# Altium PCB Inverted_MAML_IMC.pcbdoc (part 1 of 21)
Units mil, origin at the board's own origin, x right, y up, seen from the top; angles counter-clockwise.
Board outline 7677.1 x 6771.6 mil, 6 copper layers (Top Layer, Inner1, Inner2, Inner3, Inner4, Bottom Layer), stack 60.7 mil thick; 2732 components, 1531 nets, 7765 pads, 3705 vias.
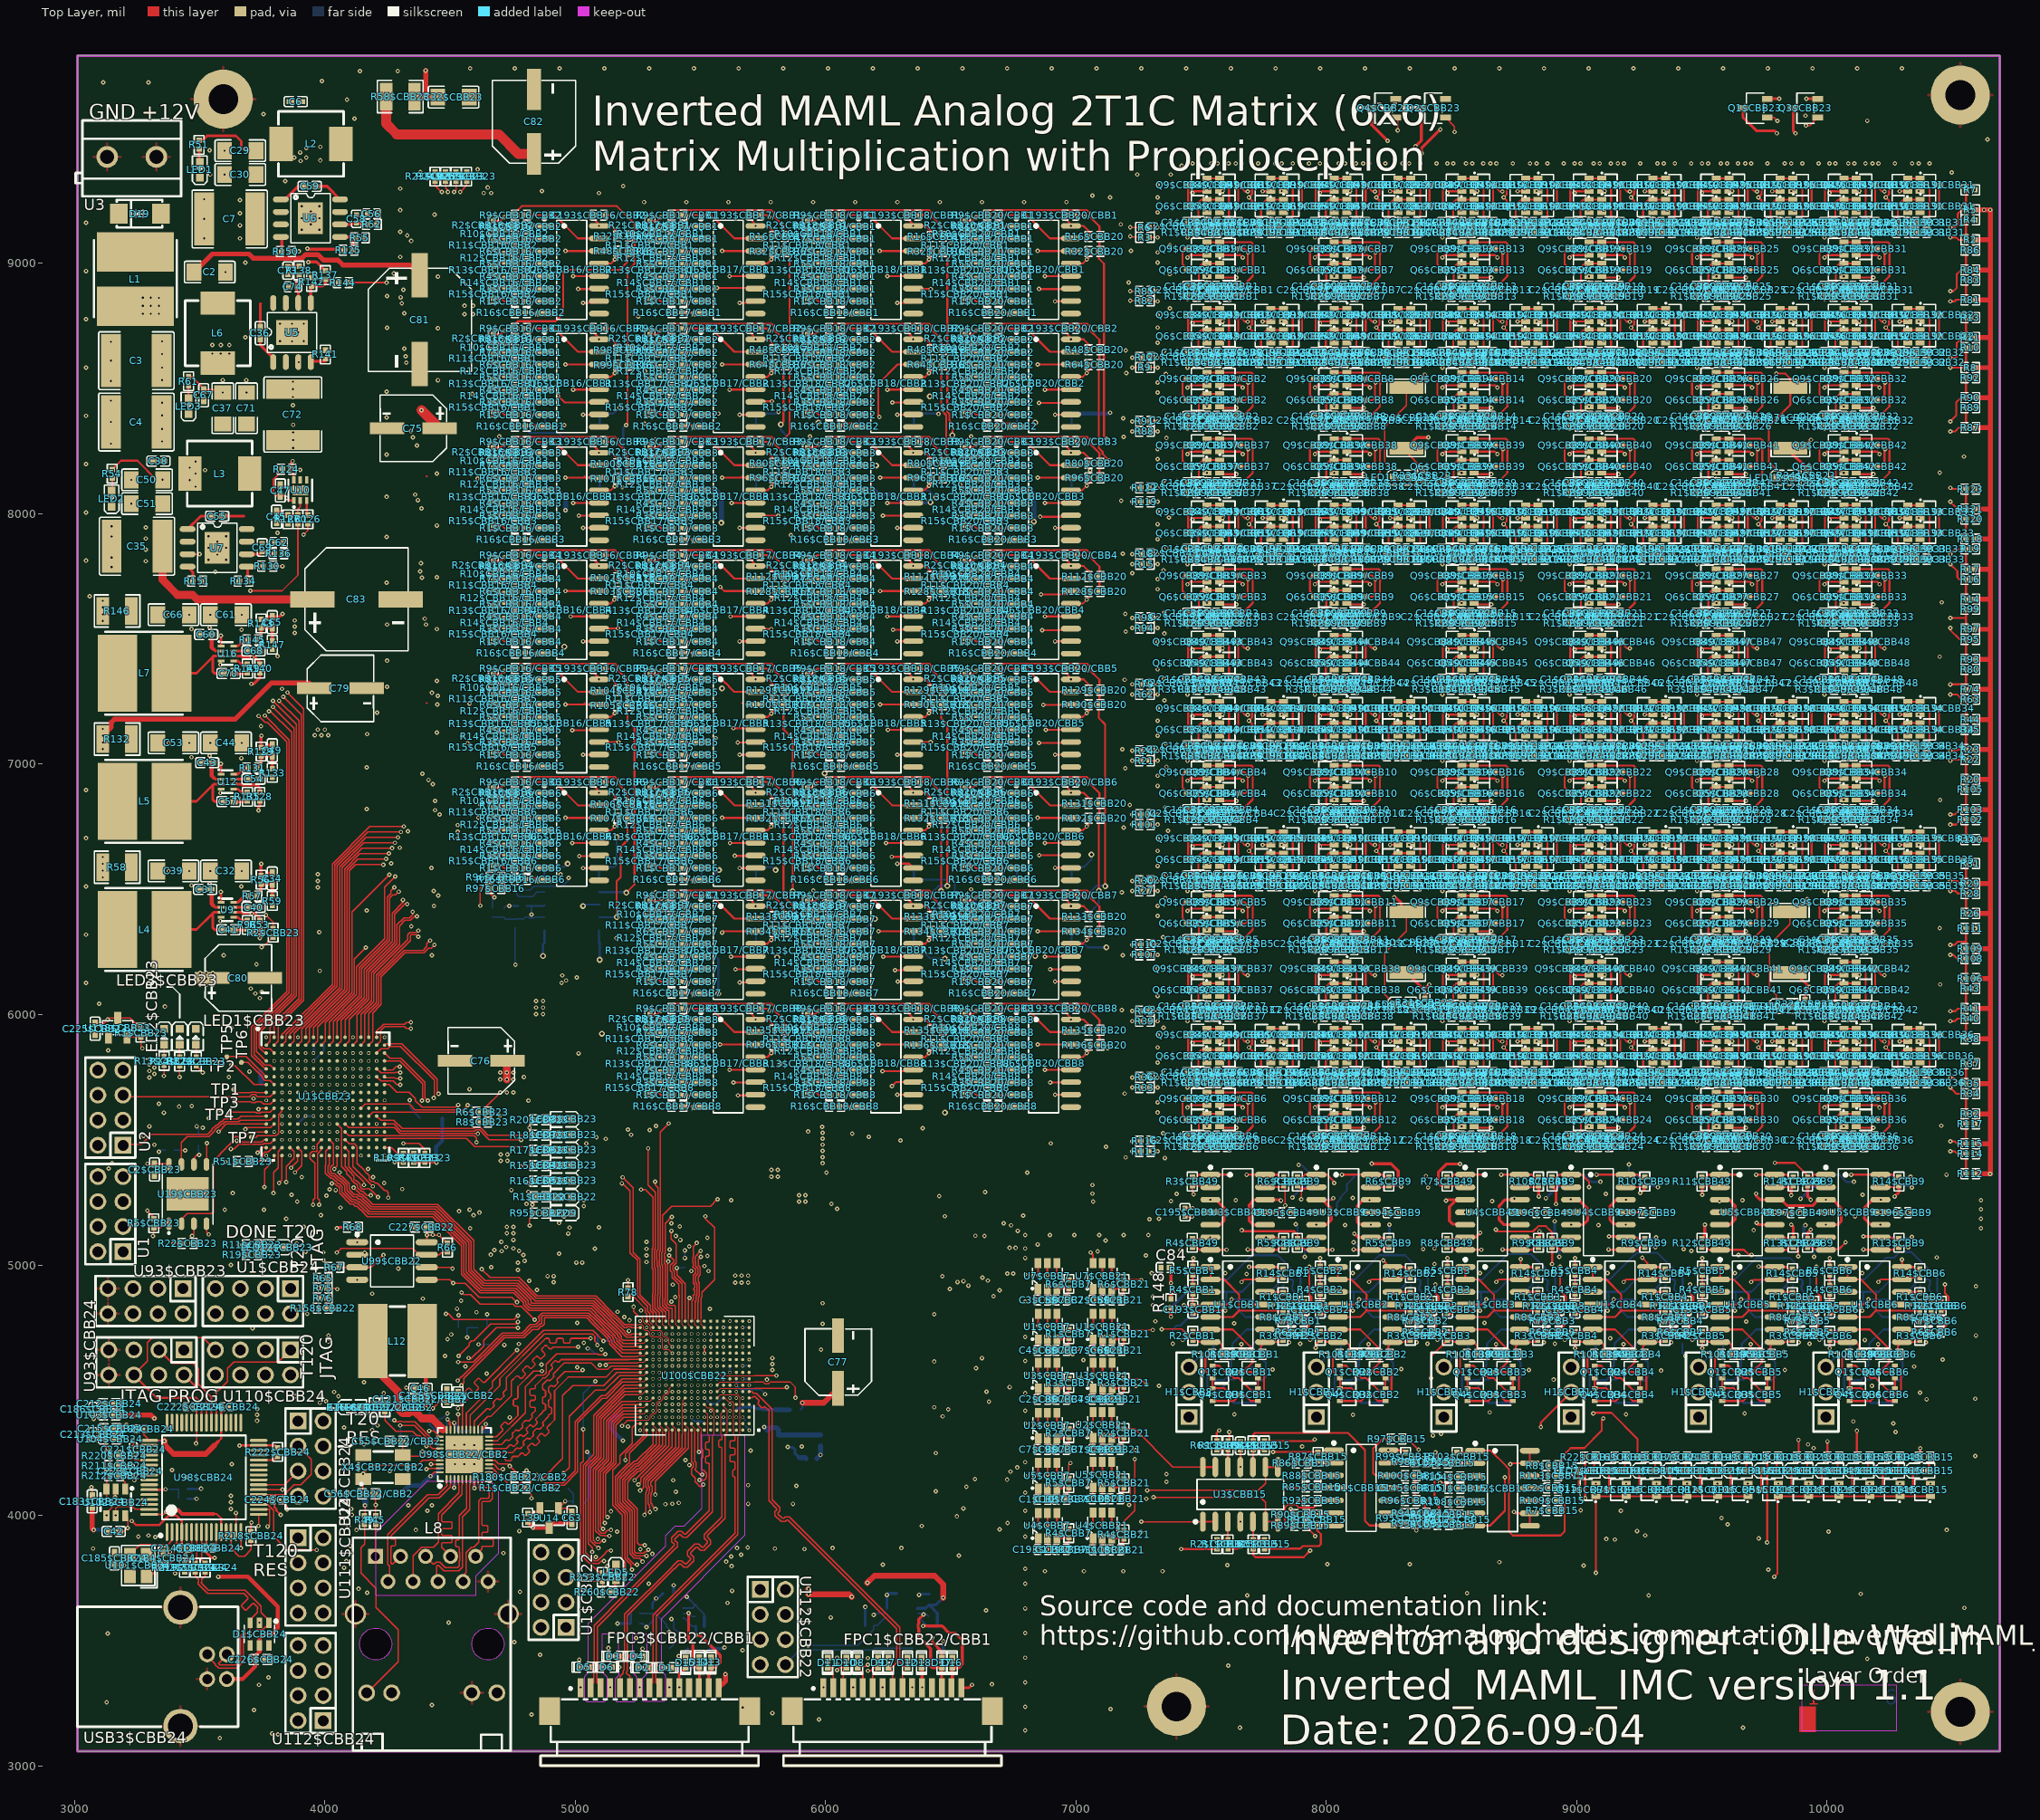
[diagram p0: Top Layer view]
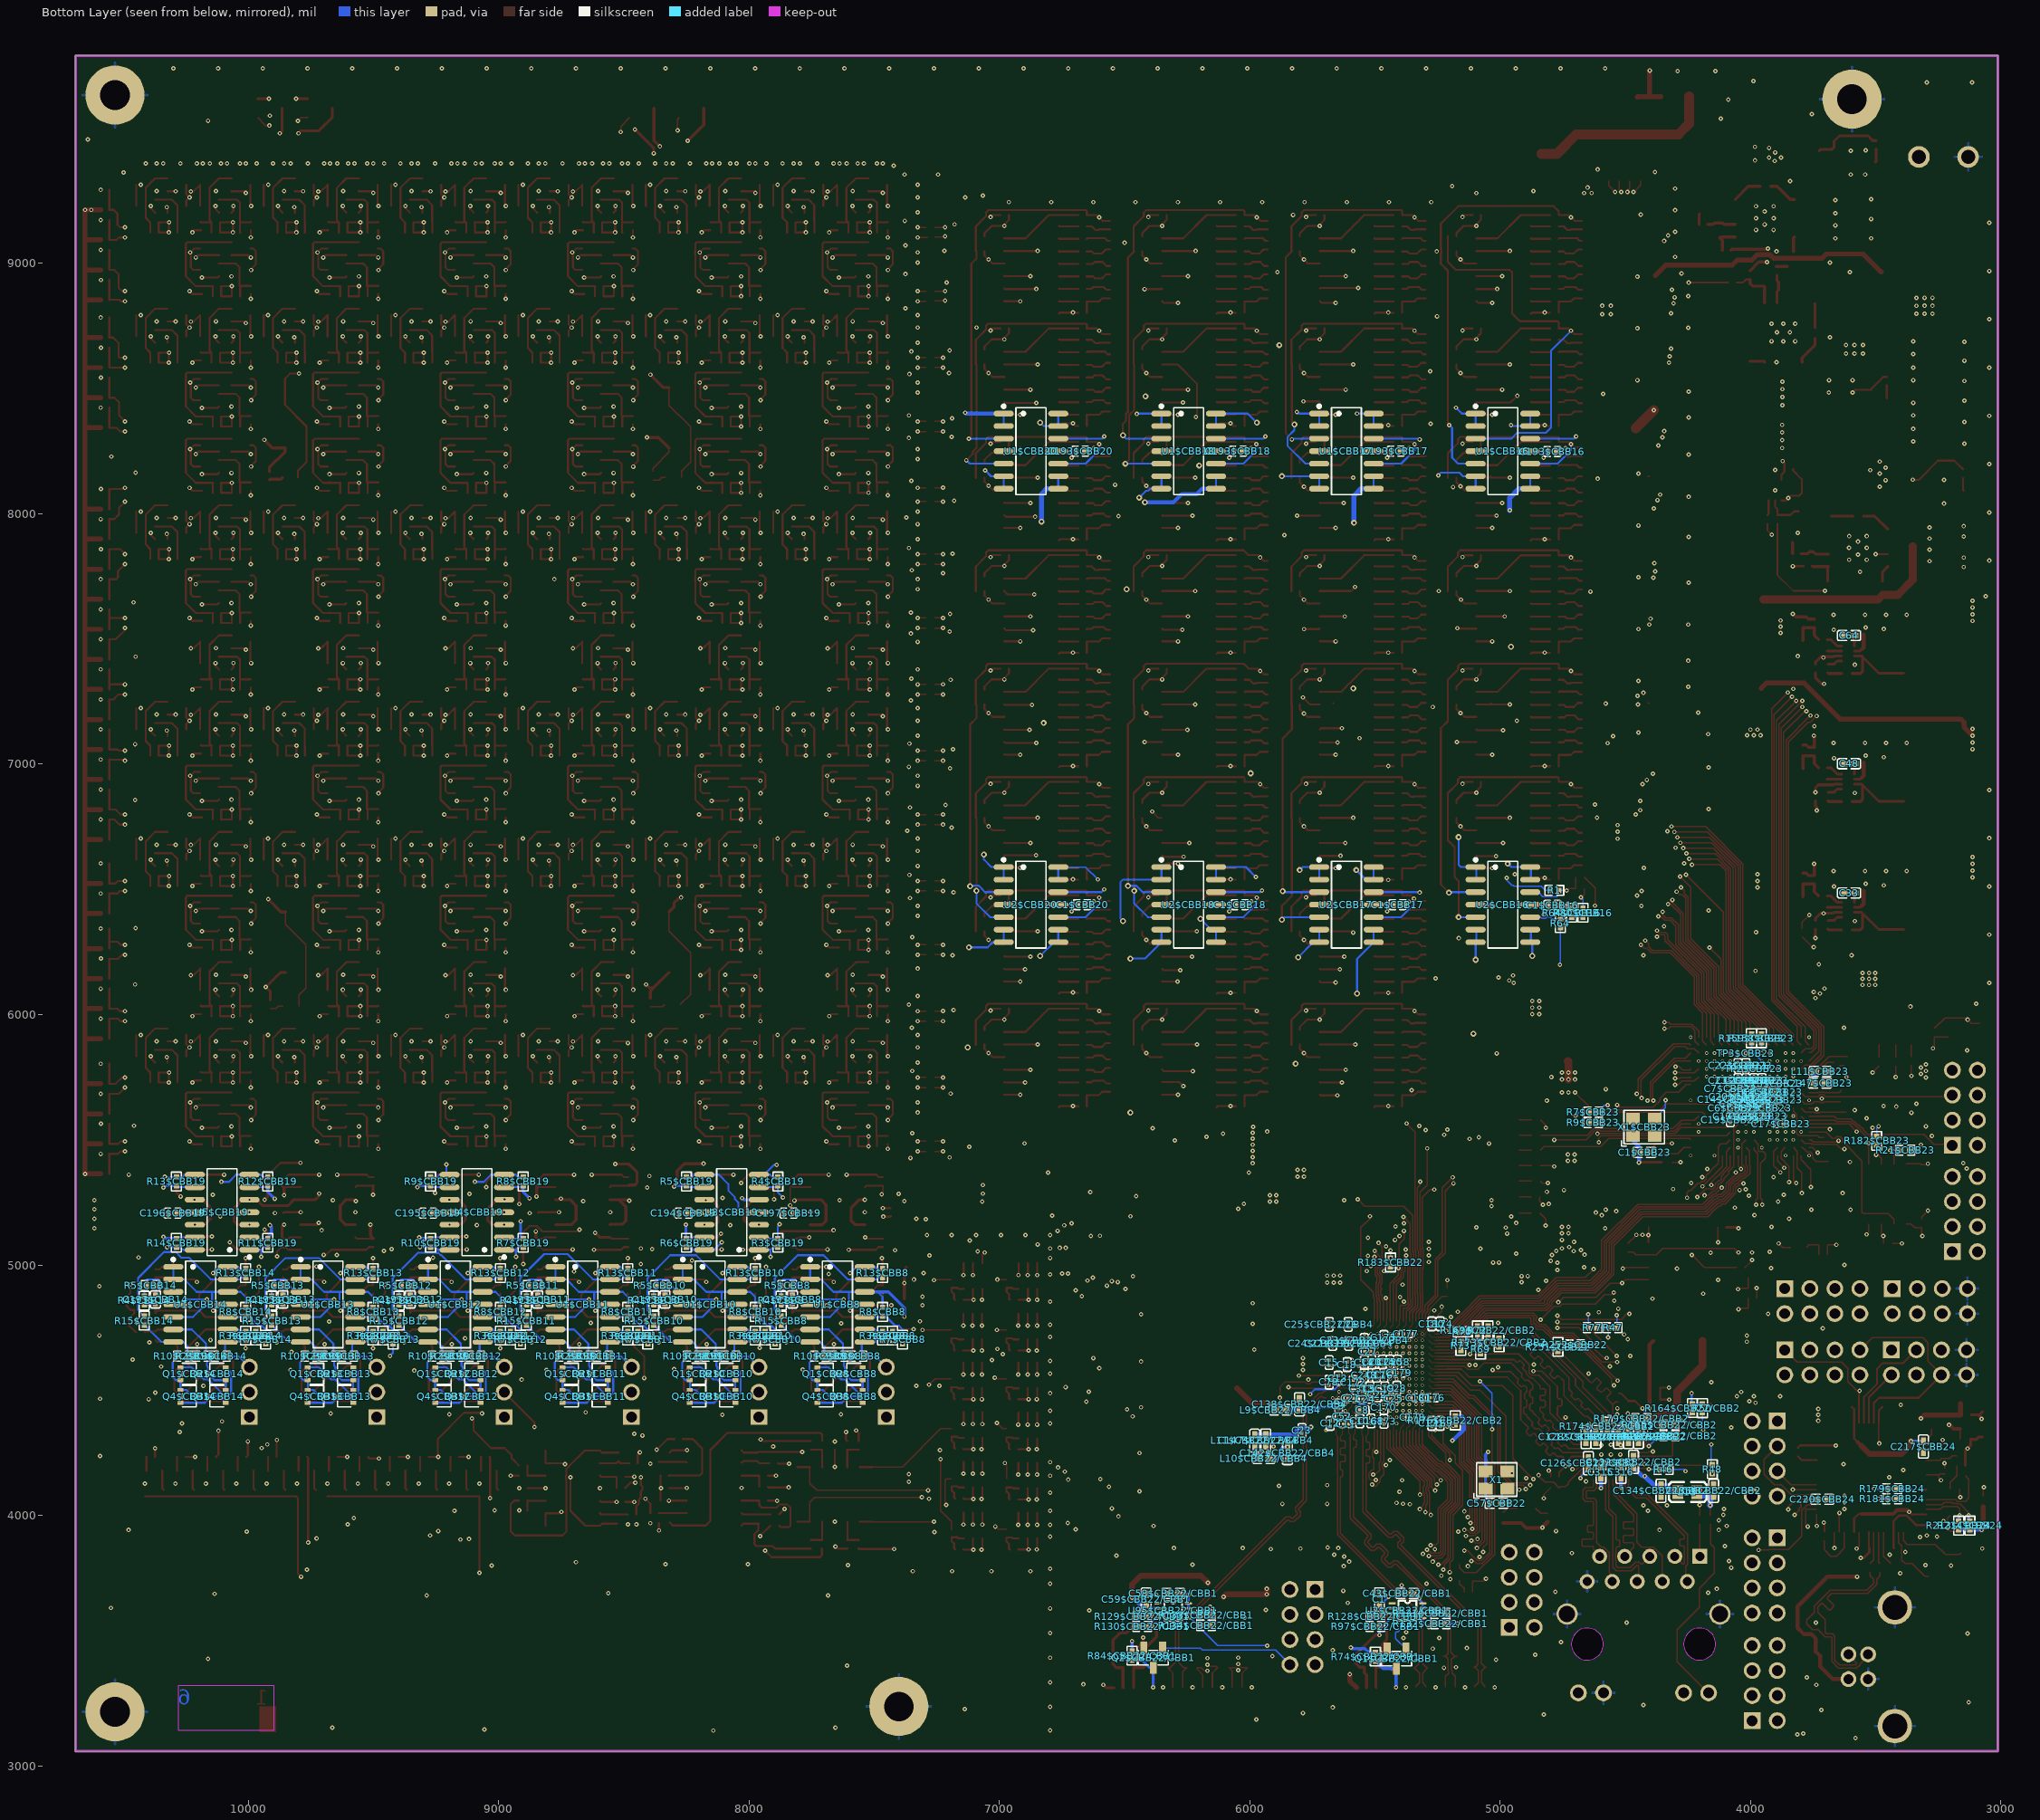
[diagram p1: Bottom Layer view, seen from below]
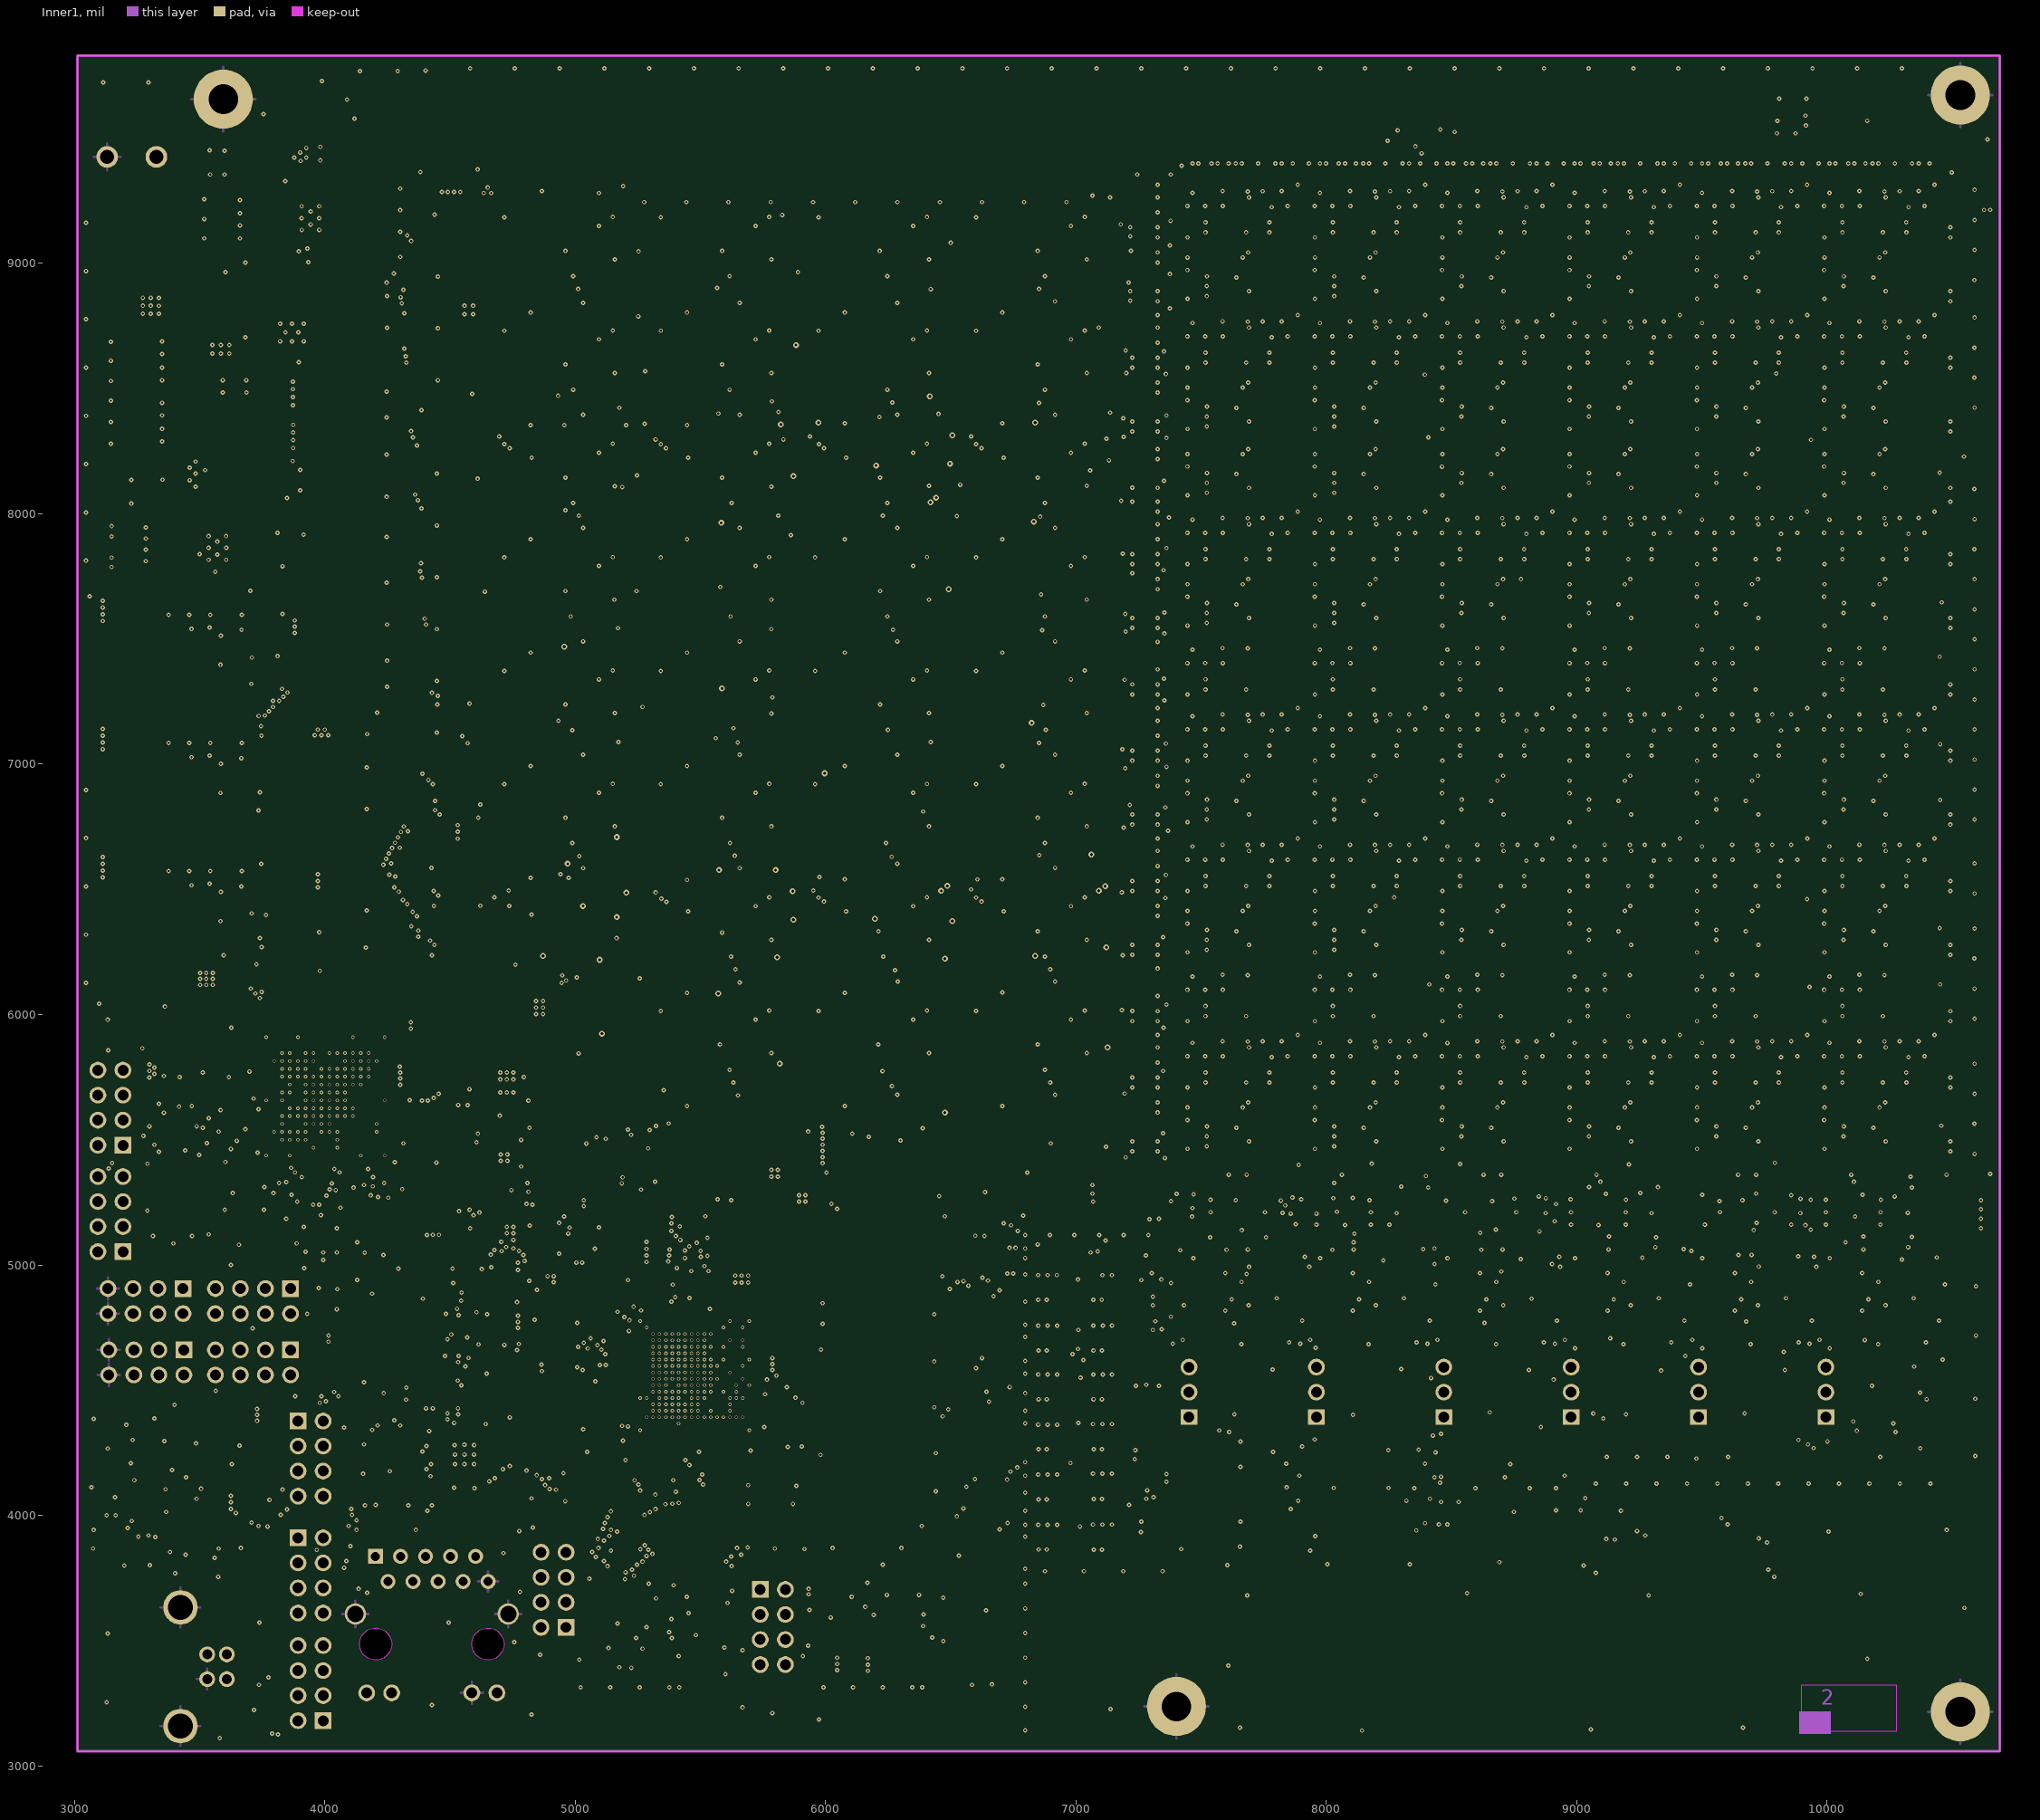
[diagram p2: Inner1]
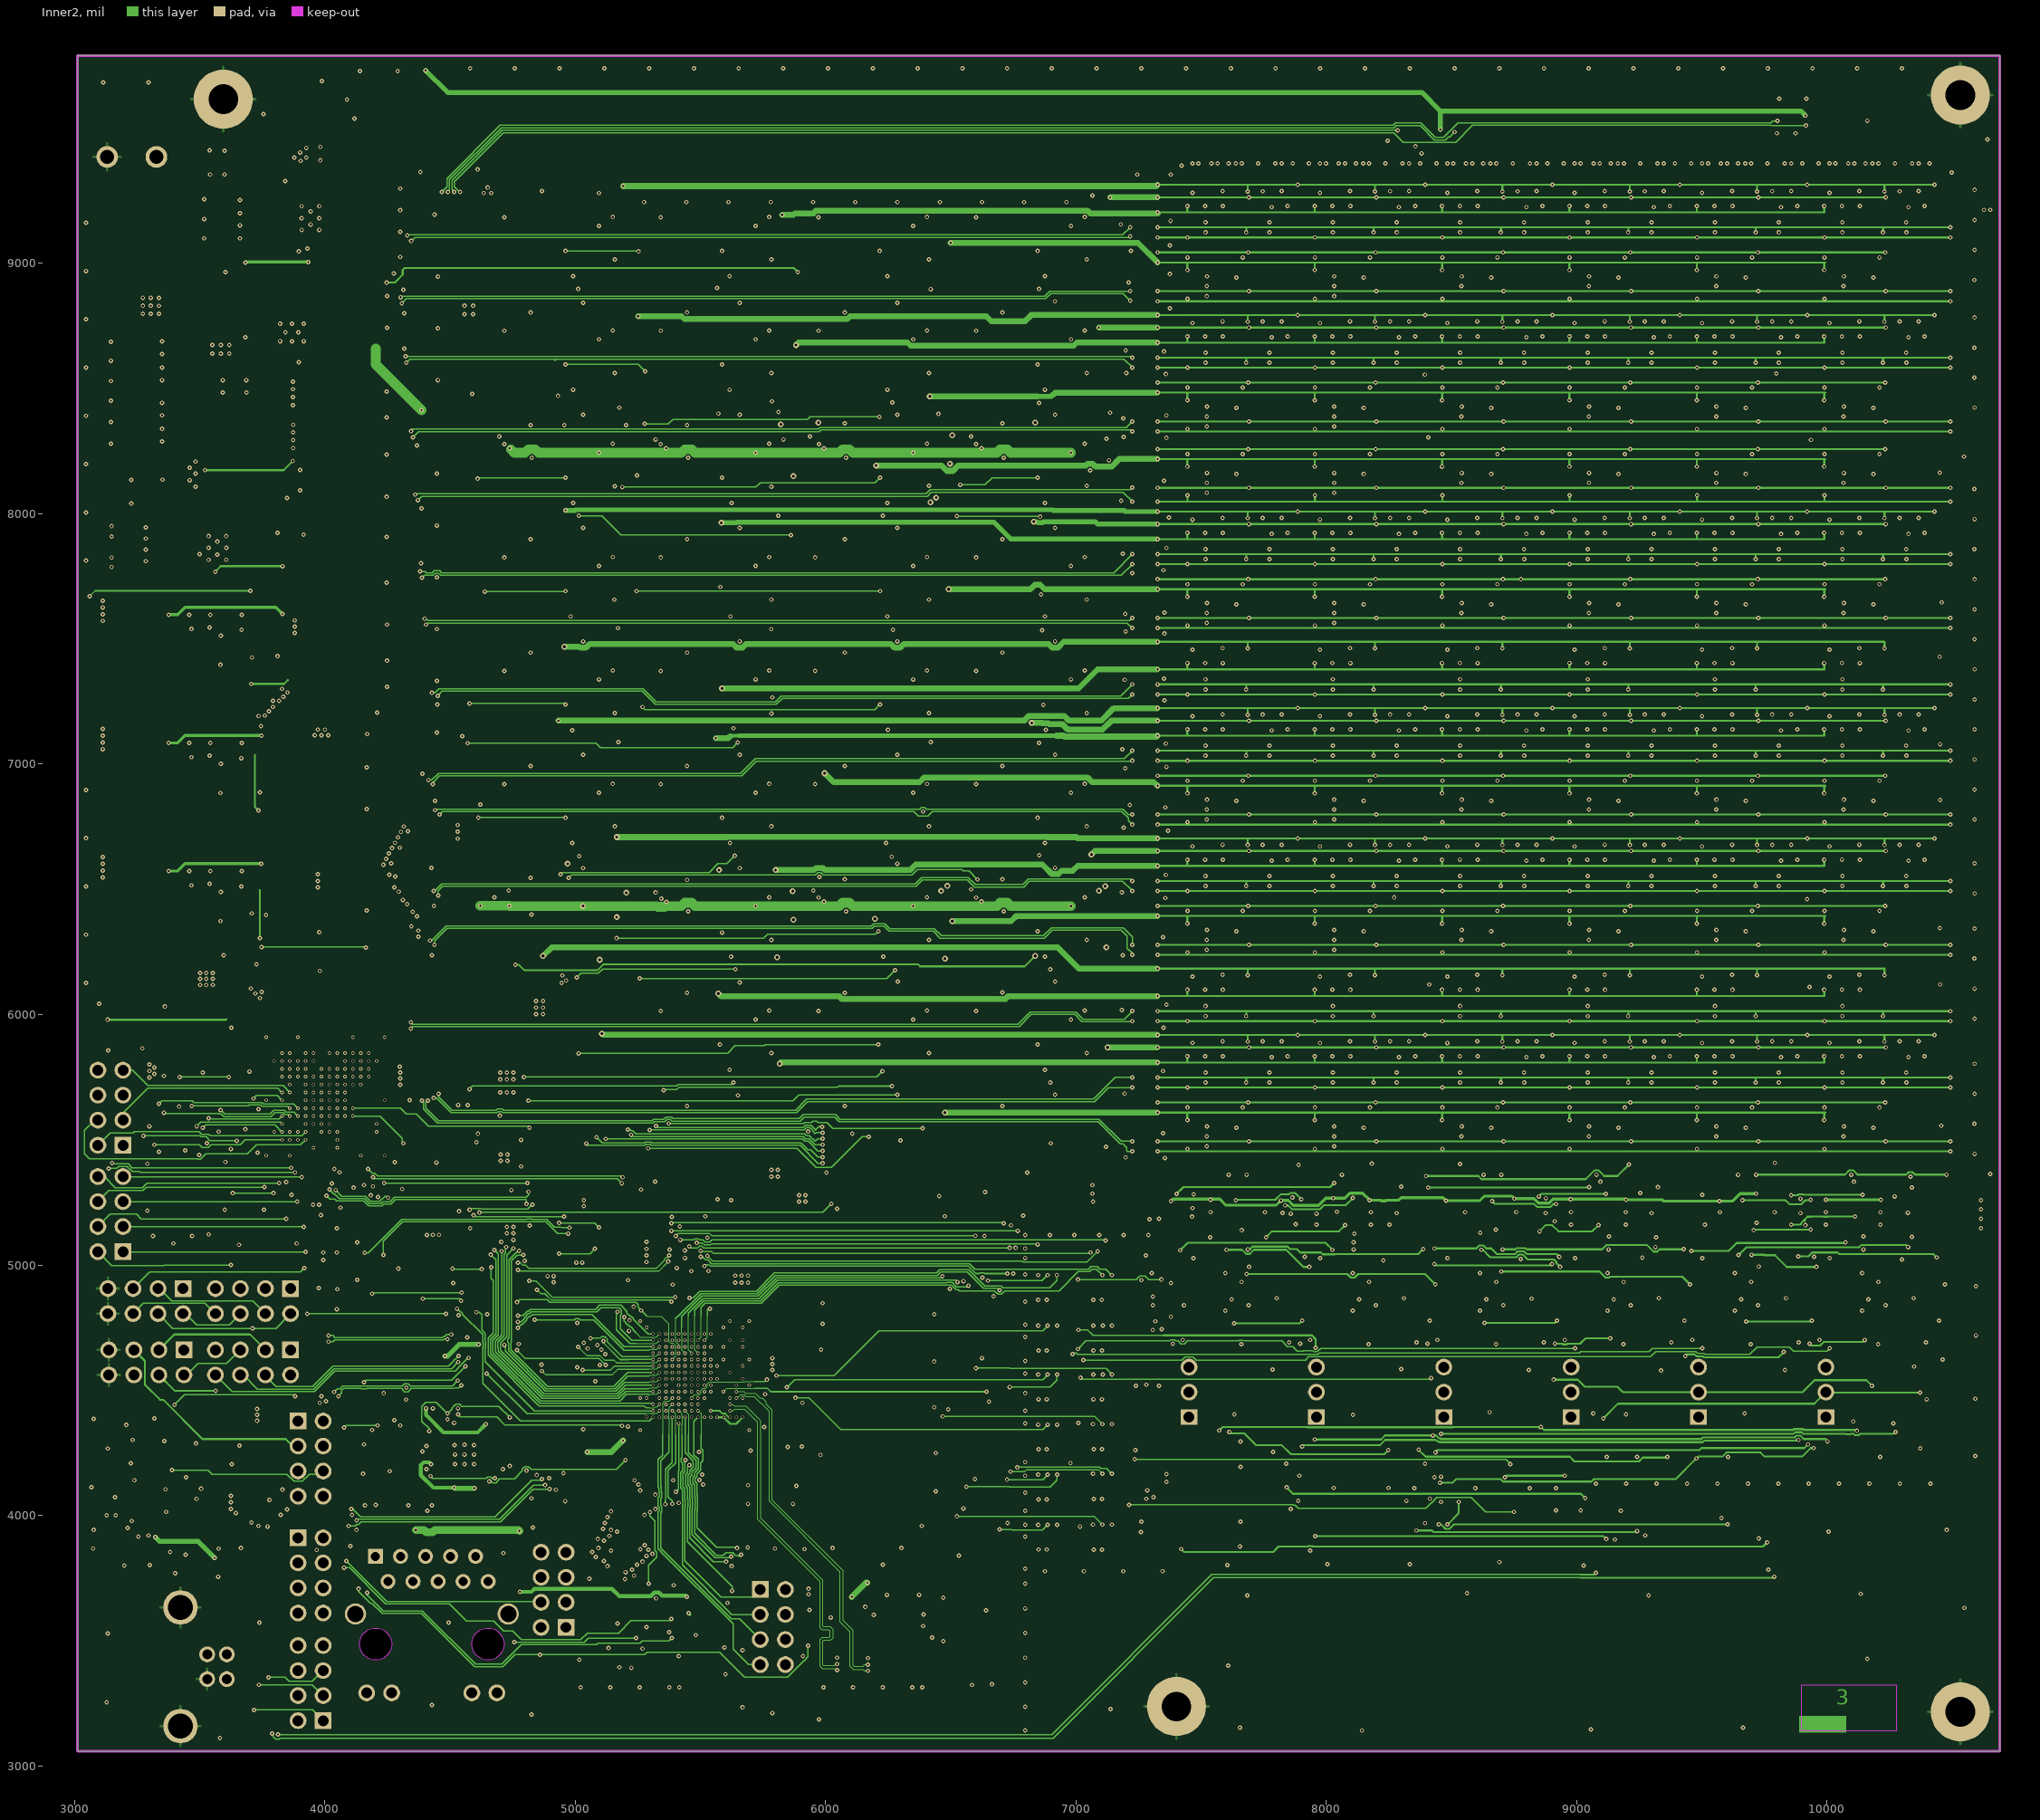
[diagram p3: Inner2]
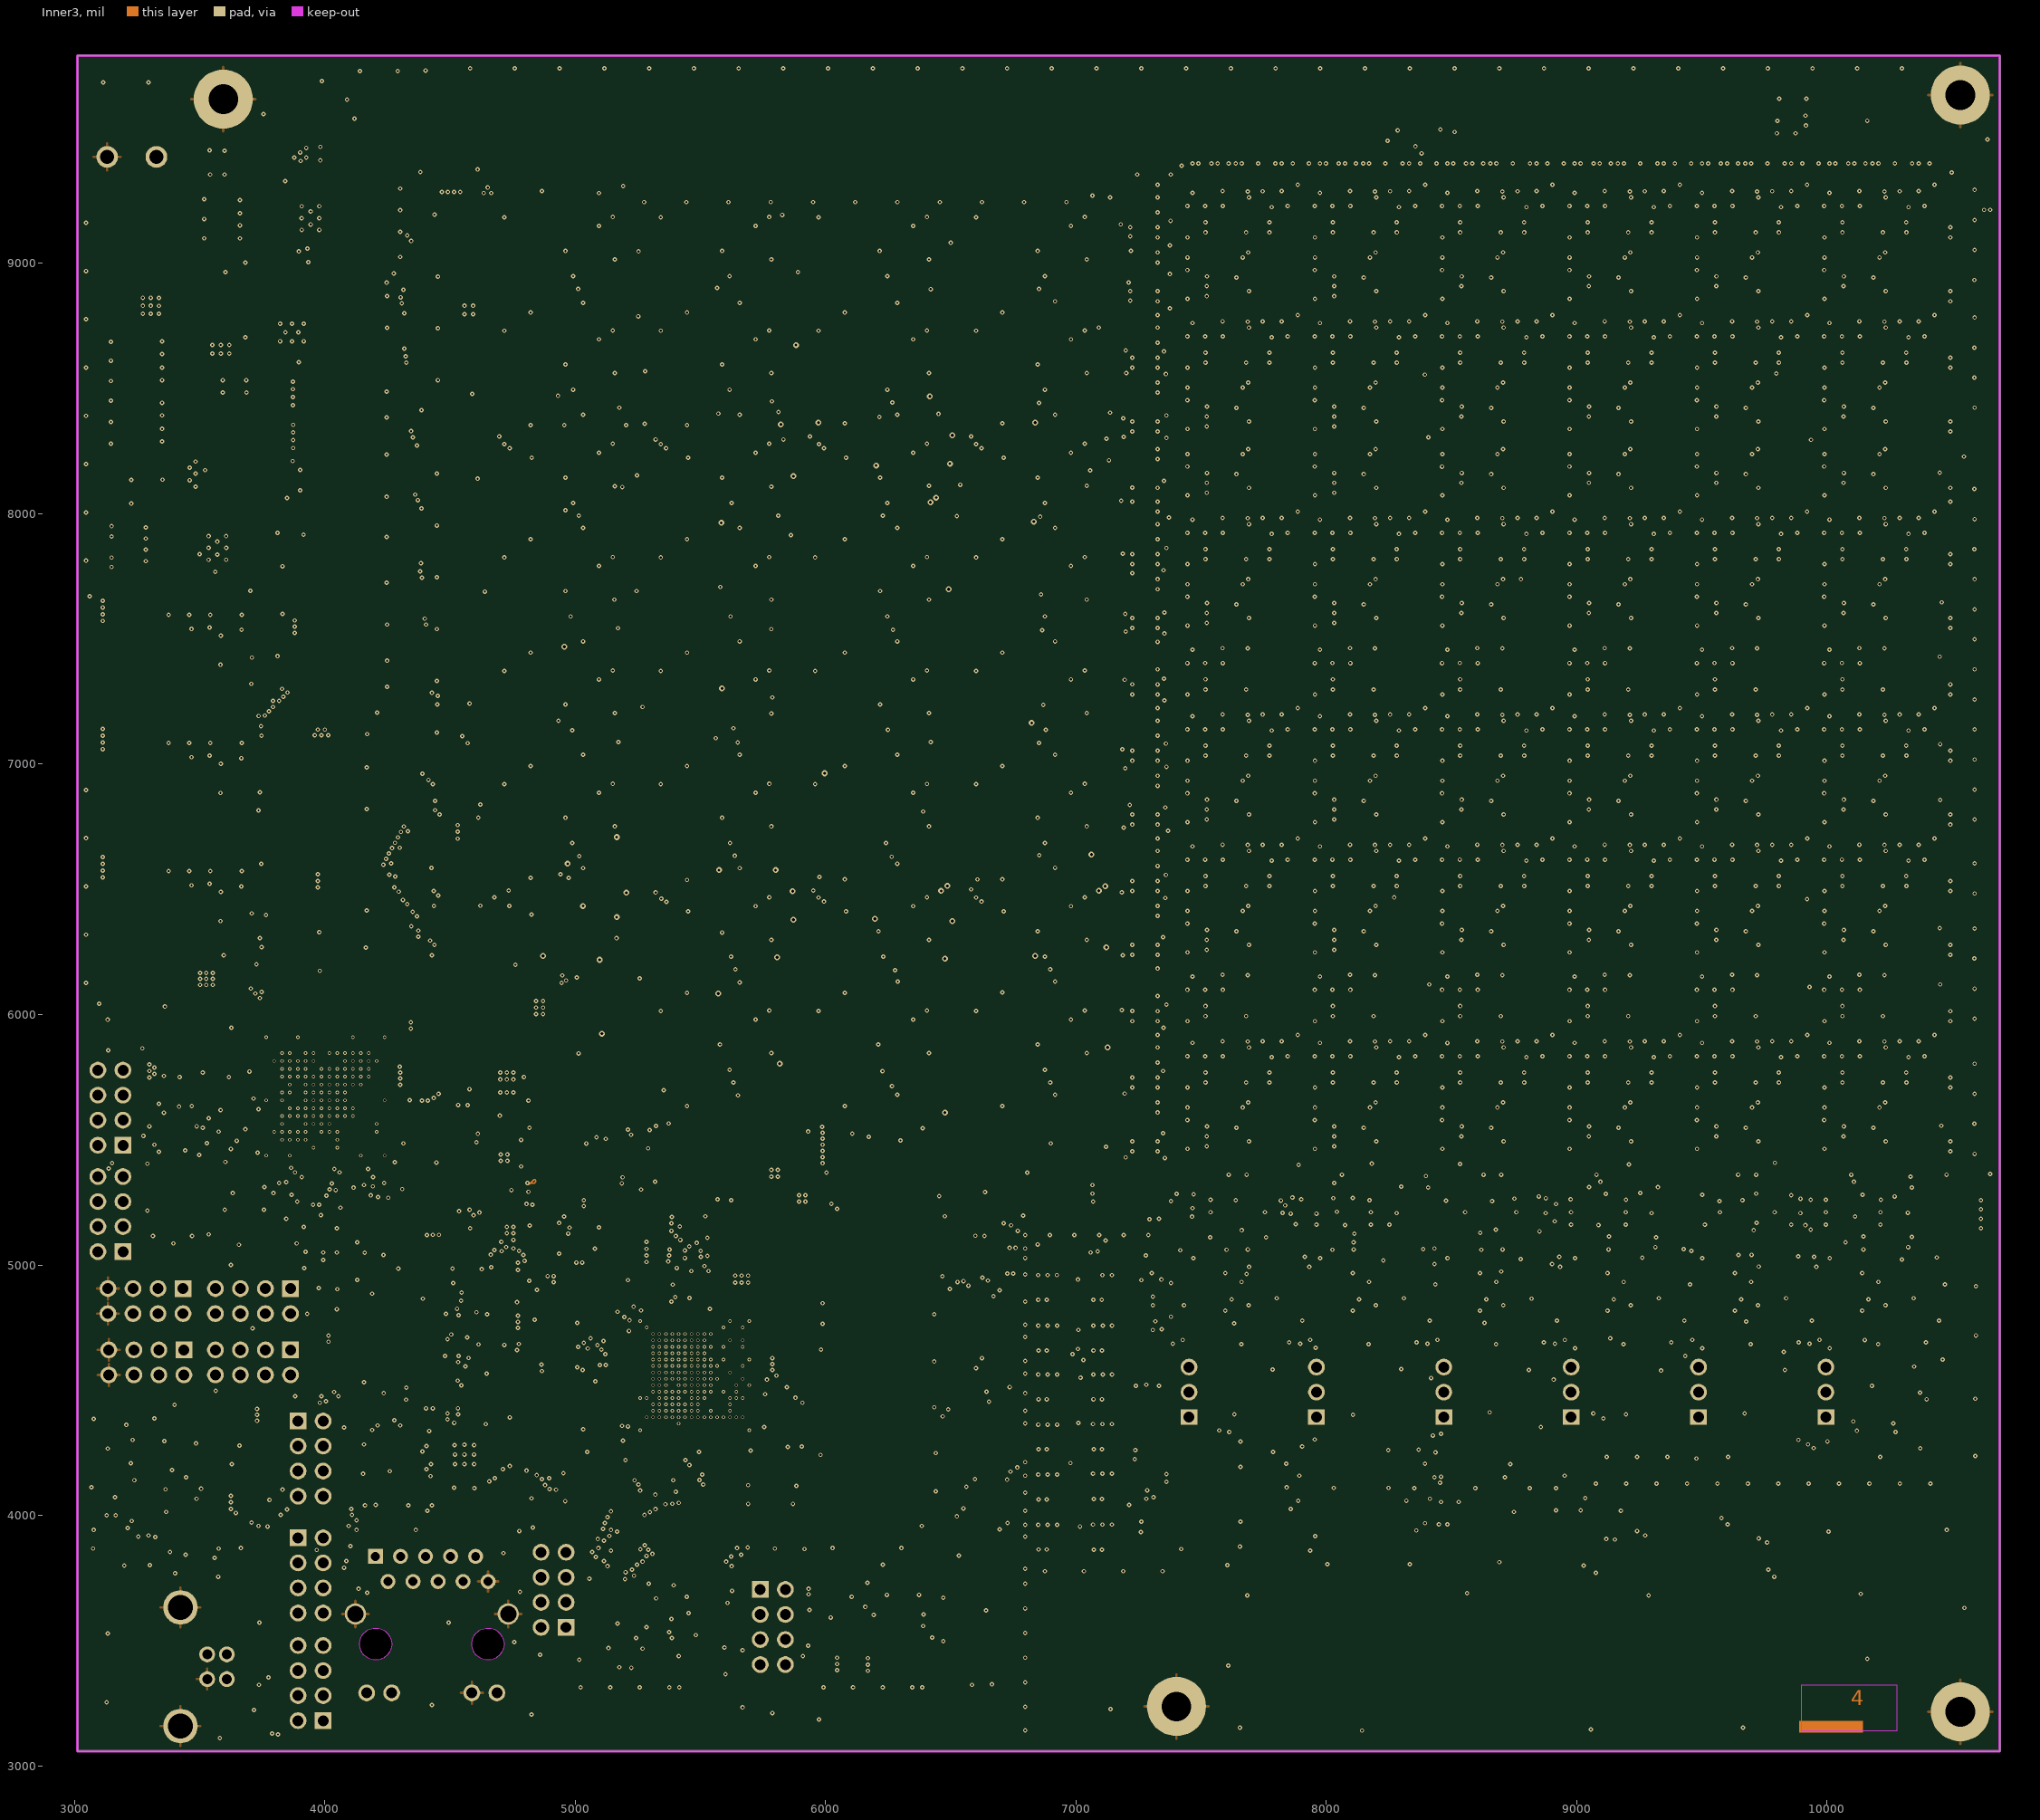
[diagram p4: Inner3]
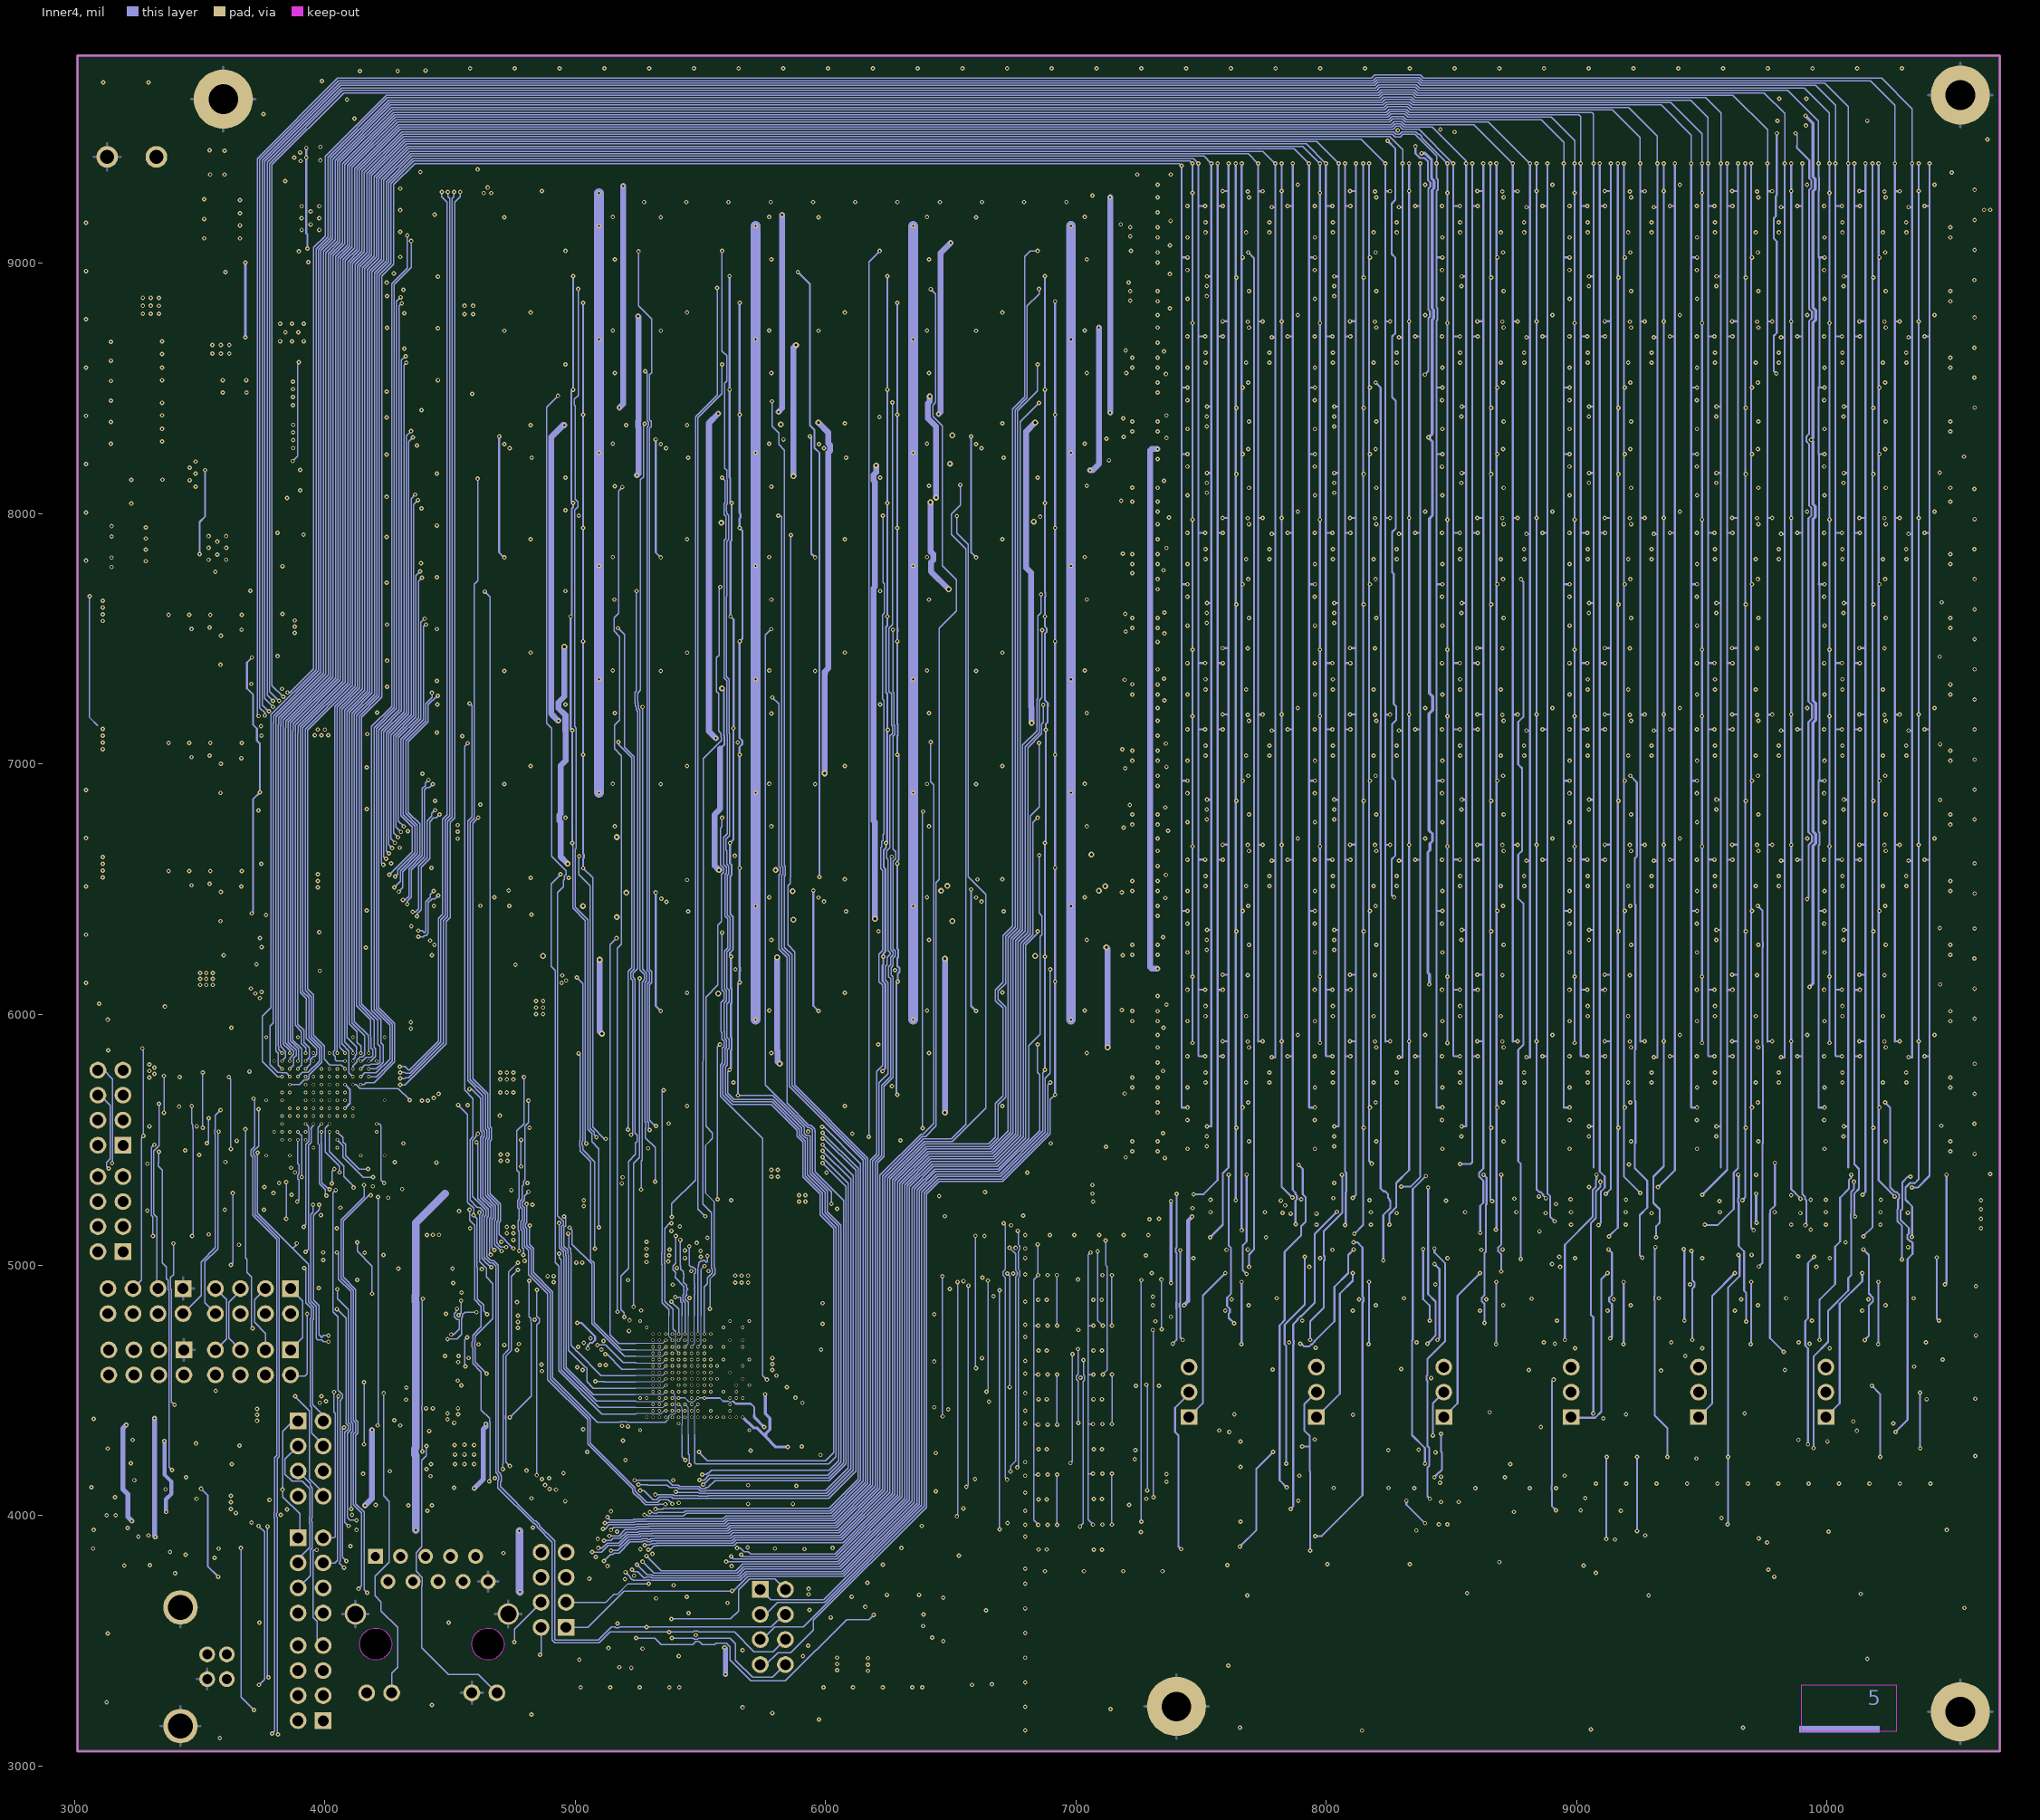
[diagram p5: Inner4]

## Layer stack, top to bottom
Top Layer: signal copper 1.4
Dielectric1: surface 3.9, 3313 RC57% 4.2mil, Dk 0
Inner1: signal copper 0.6
Dielectric2: surface 21.7, 0.55mm H/H No copper, Dk 0
Inner2: signal copper 0.6
Dielectric3: surface 4.3, 2116 RC54% 4.9mil, Dk 0
Inner3: signal copper 0.6
Dielectric4: surface 21.7, 0.55mm H/H No copper, Dk 0
Inner4: signal copper 0.6
Dielectric5: surface 3.9, 3313 RC57% 4.2mil, Dk 0
Bottom Layer: signal copper 1.4

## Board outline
3012.9,9829.8 3012.9,3058.2 10690,3058.2 10690,9829.8

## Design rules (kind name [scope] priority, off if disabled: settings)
BoardOutlineClearance copperThickness1oz [All] p0: genericclearance=10 ignorepadtopadclearanceinfootprint=FALSE except(0: Arc-SplitContinuation Track-SplitContinuation SMDPad-SplitContinuation THPad-SplitContinuation Via-SplitContinuation Fill-SplitContinuation Poly-SplitContinuation Region-SplitContinuation Text-SplitContinuation)
BoardOutlineClearance copperThickness2oz [All] p0: genericclearance=10 ignorepadtopadclearanceinfootprint=FALSE except(0: Arc-SplitContinuation Track-SplitContinuation SMDPad-SplitContinuation THPad-SplitContinuation Via-SplitContinuation Fill-SplitContinuation Poly-SplitContinuation Region-SplitContinuation Text-SplitContinuation)
BoardOutlineClearance BGA_065_SPACE [All] p0: genericclearance=10 ignorepadtopadclearanceinfootprint=FALSE except(0: Arc-SplitContinuation Track-SplitContinuation SMDPad-SplitContinuation THPad-SplitContinuation Via-SplitContinuation Fill-SplitContinuation Poly-SplitContinuation Region-SplitContinuation Text-SplitContinuation)
BoardOutlineClearance BGA_08_SPACE [All] p0: genericclearance=10 ignorepadtopadclearanceinfootprint=FALSE except(0: Arc-SplitContinuation Track-SplitContinuation SMDPad-SplitContinuation THPad-SplitContinuation Via-SplitContinuation Fill-SplitContinuation Poly-SplitContinuation Region-SplitContinuation Text-SplitContinuation)
BoardOutlineClearance Copper_BGA-065P-PLANE [All] p0: genericclearance=10 ignorepadtopadclearanceinfootprint=FALSE except(0: Arc-SplitContinuation Track-SplitContinuation SMDPad-SplitContinuation THPad-SplitContinuation Via-SplitContinuation Fill-SplitContinuation Poly-SplitContinuation Region-SplitContinuation Text-SplitContinuation)
BoardOutlineClearance Copper_BGA-08P-PLANE [All] p0: genericclearance=10 ignorepadtopadclearanceinfootprint=FALSE except(0: Arc-SplitContinuation Track-SplitContinuation SMDPad-SplitContinuation THPad-SplitContinuation Via-SplitContinuation Fill-SplitContinuation Poly-SplitContinuation Region-SplitContinuation Text-SplitContinuation)
BoardOutlineClearance Copper_BGA-OUTER_L1-L6-PLANE [All] p0: genericclearance=10 ignorepadtopadclearanceinfootprint=FALSE except(0: Arc-SplitContinuation Track-SplitContinuation SMDPad-SplitContinuation THPad-SplitContinuation Via-SplitContinuation Fill-SplitContinuation Poly-SplitContinuation Region-SplitContinuation Text-SplitContinuation)
BoardOutlineClearance Copper_copperRegion [All] p0: genericclearance=10 ignorepadtopadclearanceinfootprint=FALSE except(0: Arc-SplitContinuation Track-SplitContinuation SMDPad-SplitContinuation THPad-SplitContinuation Via-SplitContinuation Fill-SplitContinuation Poly-SplitContinuation Region-SplitContinuation Text-SplitContinuation)
BoardOutlineClearance Copper_copperRegion_36V [All] p0: genericclearance=10 ignorepadtopadclearanceinfootprint=FALSE except(0: Arc-SplitContinuation Track-SplitContinuation SMDPad-SplitContinuation THPad-SplitContinuation Via-SplitContinuation Fill-SplitContinuation Poly-SplitContinuation Region-SplitContinuation Text-SplitContinuation)
BoardOutlineClearance Copper_GND_top [All] p0: genericclearance=10 ignorepadtopadclearanceinfootprint=FALSE except(0: Arc-SplitContinuation Track-SplitContinuation SMDPad-SplitContinuation THPad-SplitContinuation Via-SplitContinuation Fill-SplitContinuation Poly-SplitContinuation Region-SplitContinuation Text-SplitContinuation)
BoardOutlineClearance Plane_innerPlane [All] p0: genericclearance=10 ignorepadtopadclearanceinfootprint=FALSE except(0: Arc-SplitContinuation Track-SplitContinuation SMDPad-SplitContinuation THPad-SplitContinuation Via-SplitContinuation Fill-SplitContinuation Poly-SplitContinuation Region-SplitContinuation Text-SplitContinuation)
BoardOutlineClearance otherClearance [All] p0: genericclearance=10 ignorepadtopadclearanceinfootprint=FALSE except(0: Arc-SplitContinuation Track-SplitContinuation SMDPad-SplitContinuation THPad-SplitContinuation Via-SplitContinuation Fill-SplitContinuation Poly-SplitContinuation Region-SplitContinuation Text-SplitContinuation)
Clearance copperThickness1oz [All] p1: gap=7 ignorepadtopadclearanceinfootprint=FALSE
Clearance copperThickness2oz [All] p1: gap=7 ignorepadtopadclearanceinfootprint=FALSE
Clearance BGA_065_SPACE [All] p1: gap=7 ignorepadtopadclearanceinfootprint=FALSE
Clearance BGA_08_SPACE [All] p1: gap=7 ignorepadtopadclearanceinfootprint=FALSE
Clearance Copper_BGA-065P-PLANE [All] p1: gap=7 ignorepadtopadclearanceinfootprint=FALSE
Clearance Copper_BGA-08P-PLANE [All] p1: gap=7 ignorepadtopadclearanceinfootprint=FALSE
Clearance Copper_BGA-OUTER_L1-L6-PLANE [All] p1: gap=7 ignorepadtopadclearanceinfootprint=FALSE
Clearance Copper_copperRegion [All] p1: gap=7 ignorepadtopadclearanceinfootprint=FALSE
Clearance Copper_copperRegion_36V [All] p1: gap=7 ignorepadtopadclearanceinfootprint=FALSE
Clearance Copper_GND_top [All] p1: gap=7 ignorepadtopadclearanceinfootprint=FALSE
Clearance Plane_innerPlane [All] p1: gap=7 ignorepadtopadclearanceinfootprint=FALSE
Clearance otherClearance [All] p1: gap=7 ignorepadtopadclearanceinfootprint=FALSE
DiffPairsRouting differentialPair [All] p1: maxuncoupledlength=10 minlimit=4.1339 maxlimit=Infinity mostfreqgap=7.874 toplayer_minwidth=3.937 toplayer_prefwidth=4.7244 toplayer_maxwidth=100 bottomlayer_minwidth=3.937 bottomlayer_prefwidth=4.7244 bottomlayer_maxwidth=100 midlayer1_minwidth=3.937 midlayer1_prefwidth=4.7244 midlayer1_maxwidth=100 midlayer2_minwidth=3.937 midlayer2_prefwidth=4.7244 midlayer2_maxwidth=100 midlayer3_minwidth=3.937 midlayer3_prefwidth=4.7244 midlayer3_maxwidth=100 midlayer4_minwidth=3.937 midlayer4_prefwidth=4.7244 midlayer4_maxwidth=100
PasteMaskExpansion pasteMaskExpansion [All] p1: expansion=0
PlaneConnect innerPlane [All] p1: planeconnectstyle=Direct reliefexpansion=20 reliefentries=4 reliefconductorwidth=10 reliefairgap=10
PolygonConnect copperRegion [All] p1: connectstyle=Relief reliefentries=4 reliefconductorwidth=10 polygonreliefangle="90 Angle" airgapwidth=10
PolygonConnect BGA-065P-PLANE [All] p1: connectstyle=Relief reliefentries=4 reliefconductorwidth=10 polygonreliefangle="90 Angle" airgapwidth=10
PolygonConnect BGA-08P-PLANE [All] p1: connectstyle=Relief reliefentries=4 reliefconductorwidth=10 polygonreliefangle="90 Angle" airgapwidth=10
PolygonConnect BGA-OUTER_L1-L6-PLANE [All] p1: connectstyle=Relief reliefentries=4 reliefconductorwidth=10 polygonreliefangle="90 Angle" airgapwidth=10
PolygonConnect copperRegion_36V [All] p1: connectstyle=Relief reliefentries=4 reliefconductorwidth=10 polygonreliefangle="90 Angle" airgapwidth=10
PolygonConnect GND_top [All] p1: connectstyle=Relief reliefentries=4 reliefconductorwidth=10 polygonreliefangle="90 Angle" airgapwidth=10
RoutingVias viaSize [All] p1: viastyle="Through Hole" holewidth=7.874 minholewidth=7.874 maxholewidth=248.0314 width=7.874 minwidth=7.874 maxwidth=248.0314
SolderMaskExpansion solderMaskExpansion [IsVia] p1: useseparateexpansions=TRUE expansion=-1000 expansionbottom=-1000
SolderMaskExpansion solderMaskExpansion [All] p2: useseparateexpansions=TRUE expansion=2.0079 expansionbottom=2.0079
Width copperThickness1oz [All] p1: maxlimit=100 minlimit=4 preferedwidth=12
Width copperThickness2oz [All] p1: maxlimit=100 minlimit=8 preferedwidth=10
Width 50ohm_sing_end [All] p1: maxlimit=10 minlimit=4 preferedwidth=6
Width 100ohm_diff [All] p1: maxlimit=100 minlimit=4 preferedwidth=5

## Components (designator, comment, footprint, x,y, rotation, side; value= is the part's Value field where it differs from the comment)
C1 "100nF" C0402#1 5482.4,3664.4 r270 bottom
C1$CBB7 "100nF" C0402#2 6867.1,4063.7 r180 top
C1$CBB9/CBB1 "100nF" C0402#3 7506.2,8908.7 r180 top
C1$CBB9/CBB2 "100nF" C0402#3 7506.2,8388.7 r180 top
C1$CBB9/CBB3 "100nF" C0402#3 7506.2,7603.7 r180 top
C1$CBB9/CBB4 "100nF" C0402#3 7506.2,6818.7 r180 top
C1$CBB9/CBB5 "100nF" C0402#3 7506.2,6298.7 r180 top
C1$CBB9/CBB6 "100nF" C0402#3 7506.2,5513.7 r180 top
C1$CBB9/CBB7 "100nF" C0402#3 8014.9,8908.7 r180 top
C1$CBB9/CBB8 "100nF" C0402#3 8014.9,8388.7 r180 top
C1$CBB9/CBB9 "100nF" C0402#3 8014.9,7603.7 r180 top
C1$CBB9/CBB10 "100nF" C0402#3 8014.9,6818.7 r180 top
C1$CBB9/CBB11 "100nF" C0402#3 8014.9,6298.7 r180 top
C1$CBB9/CBB12 "100nF" C0402#3 8014.9,5513.7 r180 top
C1$CBB9/CBB13 "100nF" C0402#3 8523.6,8908.7 r180 top
C1$CBB9/CBB14 "100nF" C0402#3 8523.6,8388.7 r180 top
C1$CBB9/CBB15 "100nF" C0402#3 8523.6,7603.7 r180 top
C1$CBB9/CBB16 "100nF" C0402#3 8523.6,6818.7 r180 top
C1$CBB9/CBB17 "100nF" C0402#3 8523.6,6298.7 r180 top
C1$CBB9/CBB18 "100nF" C0402#3 8523.6,5513.7 r180 top
C1$CBB9/CBB19 "100nF" C0402#3 9032.3,8908.7 r180 top
C1$CBB9/CBB20 "100nF" C0402#3 9032.3,8388.7 r180 top
C1$CBB9/CBB21 "100nF" C0402#3 9032.3,7603.7 r180 top
C1$CBB9/CBB22 "100nF" C0402#3 9032.3,6818.7 r180 top
C1$CBB9/CBB23 "100nF" C0402#3 9032.3,6298.7 r180 top
C1$CBB9/CBB24 "100nF" C0402#3 9032.3,5513.7 r180 top
C1$CBB9/CBB25 "100nF" C0402#3 9541,8908.7 r180 top
C1$CBB9/CBB26 "100nF" C0402#3 9541,8388.7 r180 top
C1$CBB9/CBB27 "100nF" C0402#3 9541,7603.7 r180 top
C1$CBB9/CBB28 "100nF" C0402#3 9541,6818.7 r180 top
C1$CBB9/CBB29 "100nF" C0402#3 9541,6298.7 r180 top
C1$CBB9/CBB30 "100nF" C0402#3 9541,5513.7 r180 top
C1$CBB9/CBB31 "100nF" C0402#3 10049.7,8908.7 r180 top
C1$CBB9/CBB32 "100nF" C0402#3 10049.7,8388.7 r180 top
C1$CBB9/CBB33 "100nF" C0402#3 10049.7,7603.7 r180 top
C1$CBB9/CBB34 "100nF" C0402#3 10049.7,6818.7 r180 top
C1$CBB9/CBB35 "100nF" C0402#3 10049.7,6298.7 r180 top
C1$CBB9/CBB36 "100nF" C0402#3 10049.7,5513.7 r180 top
C1$CBB9/CBB37 "100nF" C0402#3 7506.2,8123.7 r180 top
C1$CBB9/CBB38 "100nF" C0402#3 8014.9,8123.7 r180 top
C1$CBB9/CBB39 "100nF" C0402#3 8523.6,8123.7 r180 top
C1$CBB9/CBB40 "100nF" C0402#3 9032.3,8123.7 r180 top
C1$CBB9/CBB41 "100nF" C0402#3 9541,8123.7 r180 top
C1$CBB9/CBB42 "100nF" C0402#3 10049.7,8123.7 r180 top
C1$CBB16 "100nF" C0402#2 4791.7,6436.1 r180 bottom
C1$CBB17 "100nF" C0402#2 5410.2,6439.1 r180 bottom
C1$CBB18 "100nF" C0402#3 6040.2,6439.1 r180 bottom
C1$CBB19/CBB1 "100nF" C0402#3 7756.2,9163.7 r180 top
C1$CBB19/CBB2 "100nF" C0402#3 7756.2,8643.7 r180 top
C1$CBB19/CBB3 "100nF" C0402#3 7756.2,7858.7 r180 top
C1$CBB19/CBB4 "100nF" C0402#3 7756.2,7073.7 r180 top
C1$CBB19/CBB5 "100nF" C0402#3 7756.2,6553.7 r180 top
C1$CBB19/CBB6 "100nF" C0402#3 7756.2,5768.7 r180 top
C1$CBB19/CBB7 "100nF" C0402#3 8264.9,9163.7 r180 top
C1$CBB19/CBB8 "100nF" C0402#3 8264.9,8643.7 r180 top
C1$CBB19/CBB9 "100nF" C0402#3 8264.9,7858.7 r180 top
C1$CBB19/CBB10 "100nF" C0402#3 8264.9,7073.7 r180 top
C1$CBB19/CBB11 "100nF" C0402#3 8264.9,6553.7 r180 top
C1$CBB19/CBB12 "100nF" C0402#3 8264.9,5768.7 r180 top
C1$CBB19/CBB13 "100nF" C0402#3 8773.6,9163.7 r180 top
C1$CBB19/CBB14 "100nF" C0402#3 8773.6,8643.7 r180 top
C1$CBB19/CBB15 "100nF" C0402#3 8773.6,7858.7 r180 top
C1$CBB19/CBB16 "100nF" C0402#3 8773.6,7073.7 r180 top
C1$CBB19/CBB17 "100nF" C0402#3 8773.6,6553.7 r180 top
C1$CBB19/CBB18 "100nF" C0402#3 8773.6,5768.7 r180 top
C1$CBB19/CBB19 "100nF" C0402#3 9282.3,9163.7 r180 top
C1$CBB19/CBB20 "100nF" C0402#3 9282.3,8643.7 r180 top
C1$CBB19/CBB21 "100nF" C0402#3 9282.3,7858.7 r180 top
C1$CBB19/CBB22 "100nF" C0402#3 9282.3,7073.7 r180 top
C1$CBB19/CBB23 "100nF" C0402#3 9282.3,6553.7 r180 top
C1$CBB19/CBB24 "100nF" C0402#3 9282.3,5768.7 r180 top
C1$CBB19/CBB25 "100nF" C0402#3 9791,9163.7 r180 top
C1$CBB19/CBB26 "100nF" C0402#3 9791,8643.7 r180 top
C1$CBB19/CBB27 "100nF" C0402#3 9791,7858.7 r180 top
C1$CBB19/CBB28 "100nF" C0402#3 9791,7073.7 r180 top
C1$CBB19/CBB29 "100nF" C0402#3 9791,6553.7 r180 top
C1$CBB19/CBB30 "100nF" C0402#3 9791,5768.7 r180 top
C1$CBB19/CBB31 "100nF" C0402#3 10299.7,9163.7 r180 top
C1$CBB19/CBB32 "100nF" C0402#3 10299.7,8643.7 r180 top
C1$CBB19/CBB33 "100nF" C0402#3 10299.7,7858.7 r180 top
C1$CBB19/CBB34 "100nF" C0402#3 10299.7,7073.7 r180 top
C1$CBB19/CBB35 "100nF" C0402#3 10299.7,6553.7 r180 top
C1$CBB19/CBB36 "100nF" C0402#3 10299.7,5768.7 r180 top
C1$CBB20 "100nF" C0402#3 6670.1,6439.1 r180 bottom
C1$CBB21 "100nF" C0402#2 7087.1,4263.7 r180 top
C1$CBB23 "100nF" C0402#4 4424.4,5449.6 r180 bottom
C1$CBB49/CBB1 "100nF" C0402#3 7506.2,9163.7 r180 top
C1$CBB49/CBB2 "100nF" C0402#3 7506.2,8643.7 r180 top
C1$CBB49/CBB3 "100nF" C0402#3 7506.2,7858.7 r180 top
C1$CBB49/CBB4 "100nF" C0402#3 7506.2,7073.7 r180 top
C1$CBB49/CBB5 "100nF" C0402#3 7506.2,6553.7 r180 top
C1$CBB49/CBB6 "100nF" C0402#3 7506.2,5768.7 r180 top
C1$CBB49/CBB7 "100nF" C0402#3 8014.9,9163.7 r180 top
C1$CBB49/CBB8 "100nF" C0402#3 8014.9,8643.7 r180 top
C1$CBB49/CBB9 "100nF" C0402#3 8014.9,7858.7 r180 top
C1$CBB49/CBB10 "100nF" C0402#3 8014.9,7073.7 r180 top
C1$CBB49/CBB11 "100nF" C0402#3 8014.9,6553.7 r180 top
C1$CBB49/CBB12 "100nF" C0402#3 8014.9,5768.7 r180 top
C1$CBB49/CBB13 "100nF" C0402#3 8523.6,9163.7 r180 top
C1$CBB49/CBB14 "100nF" C0402#3 8523.6,8643.7 r180 top
C1$CBB49/CBB15 "100nF" C0402#3 8523.6,7858.7 r180 top
C1$CBB49/CBB16 "100nF" C0402#3 8523.6,7073.7 r180 top
C1$CBB49/CBB17 "100nF" C0402#3 8523.6,6553.7 r180 top
C1$CBB49/CBB18 "100nF" C0402#3 8523.6,5768.7 r180 top
C1$CBB49/CBB19 "100nF" C0402#3 9032.3,9163.7 r180 top
C1$CBB49/CBB20 "100nF" C0402#3 9032.3,8643.7 r180 top
C1$CBB49/CBB21 "100nF" C0402#3 9032.3,7858.7 r180 top
C1$CBB49/CBB22 "100nF" C0402#3 9032.3,7073.7 r180 top
C1$CBB49/CBB23 "100nF" C0402#3 9032.3,6553.7 r180 top
C1$CBB49/CBB24 "100nF" C0402#3 9032.3,5768.7 r180 top
C1$CBB49/CBB25 "100nF" C0402#3 9541,9163.7 r180 top
C1$CBB49/CBB26 "100nF" C0402#3 9541,8643.7 r180 top
C1$CBB49/CBB27 "100nF" C0402#3 9541,7858.7 r180 top
C1$CBB49/CBB28 "100nF" C0402#3 9541,7073.7 r180 top
C1$CBB49/CBB29 "100nF" C0402#3 9541,6553.7 r180 top
C1$CBB49/CBB30 "100nF" C0402#3 9541,5768.7 r180 top
C1$CBB49/CBB31 "100nF" C0402#3 10049.7,9163.7 r180 top
C1$CBB49/CBB32 "100nF" C0402#3 10049.7,8643.7 r180 top
C1$CBB49/CBB33 "100nF" C0402#3 10049.7,7858.7 r180 top
C1$CBB49/CBB34 "100nF" C0402#3 10049.7,7073.7 r180 top
C1$CBB49/CBB35 "100nF" C0402#3 10049.7,6553.7 r180 top
C1$CBB49/CBB36 "100nF" C0402#3 10049.7,5768.7 r180 top
C1$CBB49/CBB37 "100nF" C0402#3 7506.2,6033.7 r180 top
C1$CBB49/CBB38 "100nF" C0402#3 8014.9,6033.7 r180 top
C1$CBB49/CBB39 "100nF" C0402#3 8523.6,6033.7 r180 top
C1$CBB49/CBB40 "100nF" C0402#3 9032.3,6033.7 r180 top
C1$CBB49/CBB41 "100nF" C0402#3 9541,6033.7 r180 top
C1$CBB49/CBB42 "100nF" C0402#3 10049.7,6033.7 r180 top
C1$CBB49/CBB43 "100nF" C0402#3 7506.2,7338.7 r180 top
C1$CBB49/CBB44 "100nF" C0402#3 8014.9,7338.7 r180 top
C1$CBB49/CBB45 "100nF" C0402#3 8523.6,7338.7 r180 top
C1$CBB49/CBB46 "100nF" C0402#3 9032.3,7338.7 r180 top
C1$CBB49/CBB47 "100nF" C0402#3 9541,7338.7 r180 top
C1$CBB49/CBB48 "100nF" C0402#3 10049.7,7338.7 r180 top
C2 "1uF" C1206 3540.9,8965.4 r180 top
C2$CBB7 "100nF" C0402#2 6867.1,4463.7 r180 top
C2$CBB9/CBB1 "2.2nF" C0402#3 7446.2,8893.7 r90 top
C2$CBB9/CBB2 "2.2nF" C0402#3 7446.2,8373.7 r90 top
C2$CBB9/CBB3 "2.2nF" C0402#3 7446.2,7588.7 r90 top
C2$CBB9/CBB4 "2.2nF" C0402#3 7446.2,6803.7 r90 top
C2$CBB9/CBB5 "2.2nF" C0402#3 7446.2,6283.7 r90 top
C2$CBB9/CBB6 "2.2nF" C0402#3 7446.2,5498.7 r90 top
C2$CBB9/CBB7 "2.2nF" C0402#3 7954.9,8893.7 r90 top
C2$CBB9/CBB8 "2.2nF" C0402#3 7954.9,8373.7 r90 top
C2$CBB9/CBB9 "2.2nF" C0402#3 7954.9,7588.7 r90 top
C2$CBB9/CBB10 "2.2nF" C0402#3 7954.9,6803.7 r90 top
C2$CBB9/CBB11 "2.2nF" C0402#3 7954.9,6283.7 r90 top
C2$CBB9/CBB12 "2.2nF" C0402#3 7954.9,5498.7 r90 top
C2$CBB9/CBB13 "2.2nF" C0402#3 8463.6,8893.7 r90 top
C2$CBB9/CBB14 "2.2nF" C0402#3 8463.6,8373.7 r90 top
C2$CBB9/CBB15 "2.2nF" C0402#3 8463.6,7588.7 r90 top
C2$CBB9/CBB16 "2.2nF" C0402#3 8463.6,6803.7 r90 top
C2$CBB9/CBB17 "2.2nF" C0402#3 8463.6,6283.7 r90 top
C2$CBB9/CBB18 "2.2nF" C0402#3 8463.6,5498.7 r90 top
C2$CBB9/CBB19 "2.2nF" C0402#3 8972.3,8893.7 r90 top
C2$CBB9/CBB20 "2.2nF" C0402#3 8972.3,8373.7 r90 top
C2$CBB9/CBB21 "2.2nF" C0402#3 8972.3,7588.7 r90 top
C2$CBB9/CBB22 "2.2nF" C0402#3 8972.3,6803.7 r90 top
C2$CBB9/CBB23 "2.2nF" C0402#3 8972.3,6283.7 r90 top
C2$CBB9/CBB24 "2.2nF" C0402#3 8972.3,5498.7 r90 top
C2$CBB9/CBB25 "2.2nF" C0402#3 9481,8893.7 r90 top
C2$CBB9/CBB26 "2.2nF" C0402#3 9481,8373.7 r90 top
C2$CBB9/CBB27 "2.2nF" C0402#3 9481,7588.7 r90 top
C2$CBB9/CBB28 "2.2nF" C0402#3 9481,6803.7 r90 top
C2$CBB9/CBB29 "2.2nF" C0402#3 9481,6283.7 r90 top
C2$CBB9/CBB30 "2.2nF" C0402#3 9481,5498.7 r90 top
C2$CBB9/CBB31 "2.2nF" C0402#3 9989.7,8893.7 r90 top
C2$CBB9/CBB32 "2.2nF" C0402#3 9989.7,8373.7 r90 top
C2$CBB9/CBB33 "2.2nF" C0402#3 9989.7,7588.7 r90 top
C2$CBB9/CBB34 "2.2nF" C0402#3 9989.7,6803.7 r90 top
C2$CBB9/CBB35 "2.2nF" C0402#3 9989.7,6283.7 r90 top
C2$CBB9/CBB36 "2.2nF" C0402#3 9989.7,5498.7 r90 top
C2$CBB9/CBB37 "2.2nF" C0402#3 7446.2,8108.7 r90 top
C2$CBB9/CBB38 "2.2nF" C0402#3 7954.9,8108.7 r90 top
C2$CBB9/CBB39 "2.2nF" C0402#3 8463.6,8108.7 r90 top
C2$CBB9/CBB40 "2.2nF" C0402#3 8972.3,8108.7 r90 top
C2$CBB9/CBB41 "2.2nF" C0402#3 9481,8108.7 r90 top
C2$CBB9/CBB42 "2.2nF" C0402#3 9989.7,8108.7 r90 top
C2$CBB15 "100nF" C0402#3 8901.1,4109.2 r180 top
C2$CBB21 "100nF" C0402#2 7087.1,4860.7 r180 top
C2$CBB23 "100nF" C0402#4 3320.1,5381.3 r270 top
C2$CBB49/CBB1 "2.2nF" C0402#3 7446.2,9148.7 r90 top
C2$CBB49/CBB2 "2.2nF" C0402#3 7446.2,8628.7 r90 top
C2$CBB49/CBB3 "2.2nF" C0402#3 7446.2,7843.7 r90 top
C2$CBB49/CBB4 "2.2nF" C0402#3 7446.2,7058.7 r90 top
C2$CBB49/CBB5 "2.2nF" C0402#3 7446.2,6538.7 r90 top
C2$CBB49/CBB6 "2.2nF" C0402#3 7446.2,5753.7 r90 top
C2$CBB49/CBB7 "2.2nF" C0402#3 7954.9,9148.7 r90 top
C2$CBB49/CBB8 "2.2nF" C0402#3 7954.9,8628.7 r90 top
C2$CBB49/CBB9 "2.2nF" C0402#3 7954.9,7843.7 r90 top
C2$CBB49/CBB10 "2.2nF" C0402#3 7954.9,7058.7 r90 top
C2$CBB49/CBB11 "2.2nF" C0402#3 7954.9,6538.7 r90 top
C2$CBB49/CBB12 "2.2nF" C0402#3 7954.9,5753.7 r90 top
C2$CBB49/CBB13 "2.2nF" C0402#3 8463.6,9148.7 r90 top
C2$CBB49/CBB14 "2.2nF" C0402#3 8463.6,8628.7 r90 top
C2$CBB49/CBB15 "2.2nF" C0402#3 8463.6,7843.7 r90 top
C2$CBB49/CBB16 "2.2nF" C0402#3 8463.6,7058.7 r90 top
C2$CBB49/CBB17 "2.2nF" C0402#3 8463.6,6538.7 r90 top
C2$CBB49/CBB18 "2.2nF" C0402#3 8463.6,5753.7 r90 top
C2$CBB49/CBB19 "2.2nF" C0402#3 8972.3,9148.7 r90 top
C2$CBB49/CBB20 "2.2nF" C0402#3 8972.3,8628.7 r90 top
C2$CBB49/CBB21 "2.2nF" C0402#3 8972.3,7843.7 r90 top
C2$CBB49/CBB22 "2.2nF" C0402#3 8972.3,7058.7 r90 top
C2$CBB49/CBB23 "2.2nF" C0402#3 8972.3,6538.7 r90 top
C2$CBB49/CBB24 "2.2nF" C0402#3 8972.3,5753.7 r90 top
C2$CBB49/CBB25 "2.2nF" C0402#3 9481,9148.7 r90 top
C2$CBB49/CBB26 "2.2nF" C0402#3 9481,8628.7 r90 top
C2$CBB49/CBB27 "2.2nF" C0402#3 9481,7843.7 r90 top
C2$CBB49/CBB28 "2.2nF" C0402#3 9481,7058.7 r90 top
C2$CBB49/CBB29 "2.2nF" C0402#3 9481,6538.7 r90 top
C2$CBB49/CBB30 "2.2nF" C0402#3 9481,5753.7 r90 top
C2$CBB49/CBB31 "2.2nF" C0402#3 9989.7,9148.7 r90 top
C2$CBB49/CBB32 "2.2nF" C0402#3 9989.7,8628.7 r90 top
C2$CBB49/CBB33 "2.2nF" C0402#3 9989.7,7843.7 r90 top
C2$CBB49/CBB34 "2.2nF" C0402#3 9989.7,7058.7 r90 top
C2$CBB49/CBB35 "2.2nF" C0402#3 9989.7,6538.7 r90 top
C2$CBB49/CBB36 "2.2nF" C0402#3 9989.7,5753.7 r90 top
C2$CBB49/CBB37 "2.2nF" C0402#3 7446.2,6018.7 r90 top
C2$CBB49/CBB38 "2.2nF" C0402#3 7954.9,6018.7 r90 top
C2$CBB49/CBB39 "2.2nF" C0402#3 8463.6,6018.7 r90 top
C2$CBB49/CBB40 "2.2nF" C0402#3 8972.3,6018.7 r90 top
C2$CBB49/CBB41 "2.2nF" C0402#3 9481,6018.7 r90 top
C2$CBB49/CBB42 "2.2nF" C0402#3 9989.7,6018.7 r90 top
C2$CBB49/CBB43 "2.2nF" C0402#3 7446.2,7323.7 r90 top
C2$CBB49/CBB44 "2.2nF" C0402#3 7954.9,7323.7 r90 top
C2$CBB49/CBB45 "2.2nF" C0402#3 8463.6,7323.7 r90 top
C2$CBB49/CBB46 "2.2nF" C0402#3 8972.3,7323.7 r90 top
C2$CBB49/CBB47 "2.2nF" C0402#3 9481,7323.7 r90 top
C2$CBB49/CBB48 "2.2nF" C0402#3 9989.7,7323.7 r90 top
C3 "22uF" C2220#1 3247.9,8611.5 r0 top
C3$CBB7 "100nF" C0402#2 6867.1,4860.7 r180 top
C3$CBB9/CBB1 "100nF" C0402#2 7581.2,8908.7 r0 top
C3$CBB9/CBB2 "100nF" C0402#2 7581.2,8388.7 r0 top
C3$CBB9/CBB3 "100nF" C0402#2 7581.2,7603.7 r0 top
C3$CBB9/CBB4 "100nF" C0402#2 7581.2,6818.7 r0 top
C3$CBB9/CBB5 "100nF" C0402#2 7581.2,6298.7 r0 top
C3$CBB9/CBB6 "100nF" C0402#2 7581.2,5513.7 r0 top
C3$CBB9/CBB7 "100nF" C0402#2 8089.9,8908.7 r0 top
C3$CBB9/CBB8 "100nF" C0402#2 8089.9,8388.7 r0 top
C3$CBB9/CBB9 "100nF" C0402#2 8089.9,7603.7 r0 top
C3$CBB9/CBB10 "100nF" C0402#2 8089.9,6818.7 r0 top
C3$CBB9/CBB11 "100nF" C0402#2 8089.9,6298.7 r0 top
C3$CBB9/CBB12 "100nF" C0402#2 8089.9,5513.7 r0 top
C3$CBB9/CBB13 "100nF" C0402#2 8598.6,8908.7 r0 top
C3$CBB9/CBB14 "100nF" C0402#2 8598.6,8388.7 r0 top
C3$CBB9/CBB15 "100nF" C0402#2 8598.6,7603.7 r0 top
C3$CBB9/CBB16 "100nF" C0402#2 8598.6,6818.7 r0 top
C3$CBB9/CBB17 "100nF" C0402#2 8598.6,6298.7 r0 top
C3$CBB9/CBB18 "100nF" C0402#2 8598.6,5513.7 r0 top
C3$CBB9/CBB19 "100nF" C0402#2 9107.3,8908.7 r0 top
C3$CBB9/CBB20 "100nF" C0402#2 9107.3,8388.7 r0 top
C3$CBB9/CBB21 "100nF" C0402#2 9107.3,7603.7 r0 top
C3$CBB9/CBB22 "100nF" C0402#2 9107.3,6818.7 r0 top
C3$CBB9/CBB23 "100nF" C0402#2 9107.3,6298.7 r0 top
C3$CBB9/CBB24 "100nF" C0402#2 9107.3,5513.7 r0 top
C3$CBB9/CBB25 "100nF" C0402#2 9616,8908.7 r0 top
C3$CBB9/CBB26 "100nF" C0402#2 9616,8388.7 r0 top
C3$CBB9/CBB27 "100nF" C0402#2 9616,7603.7 r0 top
C3$CBB9/CBB28 "100nF" C0402#2 9616,6818.7 r0 top
C3$CBB9/CBB29 "100nF" C0402#2 9616,6298.7 r0 top
C3$CBB9/CBB30 "100nF" C0402#2 9616,5513.7 r0 top
C3$CBB9/CBB31 "100nF" C0402#2 10124.7,8908.7 r0 top
C3$CBB9/CBB32 "100nF" C0402#2 10124.7,8388.7 r0 top
C3$CBB9/CBB33 "100nF" C0402#2 10124.7,7603.7 r0 top
C3$CBB9/CBB34 "100nF" C0402#2 10124.7,6818.7 r0 top
C3$CBB9/CBB35 "100nF" C0402#2 10124.7,6298.7 r0 top
C3$CBB9/CBB36 "100nF" C0402#2 10124.7,5513.7 r0 top
C3$CBB9/CBB37 "100nF" C0402#2 7581.2,8123.7 r0 top
C3$CBB9/CBB38 "100nF" C0402#2 8089.9,8123.7 r0 top
C3$CBB9/CBB39 "100nF" C0402#2 8598.6,8123.7 r0 top
C3$CBB9/CBB40 "100nF" C0402#2 9107.3,8123.7 r0 top
C3$CBB9/CBB41 "100nF" C0402#2 9616,8123.7 r0 top
C3$CBB9/CBB42 "100nF" C0402#2 10124.7,8123.7 r0 top
C3$CBB19/CBB1 "100nF" C0402#2 7831.2,9163.7 r0 top
C3$CBB19/CBB2 "100nF" C0402#2 7831.2,8643.7 r0 top
C3$CBB19/CBB3 "100nF" C0402#2 7831.2,7858.7 r0 top
C3$CBB19/CBB4 "100nF" C0402#2 7831.2,7073.7 r0 top
C3$CBB19/CBB5 "100nF" C0402#2 7831.2,6553.7 r0 top
C3$CBB19/CBB6 "100nF" C0402#2 7831.2,5768.7 r0 top
C3$CBB19/CBB7 "100nF" C0402#2 8339.9,9163.7 r0 top
C3$CBB19/CBB8 "100nF" C0402#2 8339.9,8643.7 r0 top
C3$CBB19/CBB9 "100nF" C0402#2 8339.9,7858.7 r0 top
C3$CBB19/CBB10 "100nF" C0402#2 8339.9,7073.7 r0 top
C3$CBB19/CBB11 "100nF" C0402#2 8339.9,6553.7 r0 top
C3$CBB19/CBB12 "100nF" C0402#2 8339.9,5768.7 r0 top
C3$CBB19/CBB13 "100nF" C0402#2 8848.6,9163.7 r0 top
C3$CBB19/CBB14 "100nF" C0402#2 8848.6,8643.7 r0 top
C3$CBB19/CBB15 "100nF" C0402#2 8848.6,7858.7 r0 top
C3$CBB19/CBB16 "100nF" C0402#2 8848.6,7073.7 r0 top
C3$CBB19/CBB17 "100nF" C0402#2 8848.6,6553.7 r0 top
C3$CBB19/CBB18 "100nF" C0402#2 8848.6,5768.7 r0 top
C3$CBB19/CBB19 "100nF" C0402#2 9357.3,9163.7 r0 top
C3$CBB19/CBB20 "100nF" C0402#2 9357.3,8643.7 r0 top
C3$CBB19/CBB21 "100nF" C0402#2 9357.3,7858.7 r0 top
C3$CBB19/CBB22 "100nF" C0402#2 9357.3,7073.7 r0 top
C3$CBB19/CBB23 "100nF" C0402#2 9357.3,6553.7 r0 top
C3$CBB19/CBB24 "100nF" C0402#2 9357.3,5768.7 r0 top
C3$CBB19/CBB25 "100nF" C0402#2 9866,9163.7 r0 top
C3$CBB19/CBB26 "100nF" C0402#2 9866,8643.7 r0 top
C3$CBB19/CBB27 "100nF" C0402#2 9866,7858.7 r0 top
C3$CBB19/CBB28 "100nF" C0402#2 9866,7073.7 r0 top
C3$CBB19/CBB29 "100nF" C0402#2 9866,6553.7 r0 top
C3$CBB19/CBB30 "100nF" C0402#2 9866,5768.7 r0 top
C3$CBB19/CBB31 "100nF" C0402#2 10374.7,9163.7 r0 top
C3$CBB19/CBB32 "100nF" C0402#2 10374.7,8643.7 r0 top
C3$CBB19/CBB33 "100nF" C0402#2 10374.7,7858.7 r0 top
C3$CBB19/CBB34 "100nF" C0402#2 10374.7,7073.7 r0 top
C3$CBB19/CBB35 "100nF" C0402#2 10374.7,6553.7 r0 top
C3$CBB19/CBB36 "100nF" C0402#2 10374.7,5768.7 r0 top
C3$CBB21 "100nF" C0402#2 7087.1,4065.7 r180 top
C3$CBB23 "100nF" C0201 4018.8,5796.9 r90 bottom
C3$CBB49/CBB1 "100nF" C0402#2 7586.2,9163.7 r0 top
C3$CBB49/CBB2 "100nF" C0402#2 7586.2,8643.7 r0 top
C3$CBB49/CBB3 "100nF" C0402#2 7586.2,7858.7 r0 top
C3$CBB49/CBB4 "100nF" C0402#2 7586.2,7073.7 r0 top
C3$CBB49/CBB5 "100nF" C0402#2 7586.2,6553.7 r0 top
C3$CBB49/CBB6 "100nF" C0402#2 7586.2,5768.7 r0 top
C3$CBB49/CBB7 "100nF" C0402#2 8094.9,9163.7 r0 top
C3$CBB49/CBB8 "100nF" C0402#2 8094.9,8643.7 r0 top
C3$CBB49/CBB9 "100nF" C0402#2 8094.9,7858.7 r0 top
C3$CBB49/CBB10 "100nF" C0402#2 8094.9,7073.7 r0 top
C3$CBB49/CBB11 "100nF" C0402#2 8094.9,6553.7 r0 top
C3$CBB49/CBB12 "100nF" C0402#2 8094.9,5768.7 r0 top
C3$CBB49/CBB13 "100nF" C0402#2 8603.6,9163.7 r0 top
C3$CBB49/CBB14 "100nF" C0402#2 8603.6,8643.7 r0 top
C3$CBB49/CBB15 "100nF" C0402#2 8603.6,7858.7 r0 top
C3$CBB49/CBB16 "100nF" C0402#2 8603.6,7073.7 r0 top
C3$CBB49/CBB17 "100nF" C0402#2 8603.6,6553.7 r0 top
C3$CBB49/CBB18 "100nF" C0402#2 8603.6,5768.7 r0 top
C3$CBB49/CBB19 "100nF" C0402#2 9112.3,9163.7 r0 top
C3$CBB49/CBB20 "100nF" C0402#2 9112.3,8643.7 r0 top
C3$CBB49/CBB21 "100nF" C0402#2 9112.3,7858.7 r0 top
C3$CBB49/CBB22 "100nF" C0402#2 9112.3,7073.7 r0 top
C3$CBB49/CBB23 "100nF" C0402#2 9112.3,6553.7 r0 top
C3$CBB49/CBB24 "100nF" C0402#2 9112.3,5768.7 r0 top
C3$CBB49/CBB25 "100nF" C0402#2 9621,9163.7 r0 top
C3$CBB49/CBB26 "100nF" C0402#2 9621,8643.7 r0 top
C3$CBB49/CBB27 "100nF" C0402#2 9621,7858.7 r0 top
C3$CBB49/CBB28 "100nF" C0402#2 9621,7073.7 r0 top
C3$CBB49/CBB29 "100nF" C0402#2 9621,6553.7 r0 top
C3$CBB49/CBB30 "100nF" C0402#2 9621,5768.7 r0 top
C3$CBB49/CBB31 "100nF" C0402#2 10129.7,9163.7 r0 top
C3$CBB49/CBB32 "100nF" C0402#2 10129.7,8643.7 r0 top
C3$CBB49/CBB33 "100nF" C0402#2 10129.7,7858.7 r0 top
C3$CBB49/CBB34 "100nF" C0402#2 10129.7,7073.7 r0 top
C3$CBB49/CBB35 "100nF" C0402#2 10129.7,6553.7 r0 top
C3$CBB49/CBB36 "100nF" C0402#2 10129.7,5768.7 r0 top
C3$CBB49/CBB37 "100nF" C0402#2 7586.2,6033.7 r0 top
C3$CBB49/CBB38 "100nF" C0402#2 8094.9,6033.7 r0 top
C3$CBB49/CBB39 "100nF" C0402#2 8603.6,6033.7 r0 top
C3$CBB49/CBB40 "100nF" C0402#2 9112.3,6033.7 r0 top
C3$CBB49/CBB41 "100nF" C0402#2 9621,6033.7 r0 top
C3$CBB49/CBB42 "100nF" C0402#2 10129.7,6033.7 r0 top
C3$CBB49/CBB43 "100nF" C0402#2 7586.2,7338.7 r0 top
C3$CBB49/CBB44 "100nF" C0402#2 8094.9,7338.7 r0 top
C3$CBB49/CBB45 "100nF" C0402#2 8603.6,7338.7 r0 top
C3$CBB49/CBB46 "100nF" C0402#2 9112.3,7338.7 r0 top
C3$CBB49/CBB47 "100nF" C0402#2 9621,7338.7 r0 top
C3$CBB49/CBB48 "100nF" C0402#2 10129.7,7338.7 r0 top
C4 "22uF" C2220#1 3247.9,8366.5 r0 top
C4$CBB7 "100nF" C0402#2 6867.1,4658.7 r180 top
C4$CBB9/CBB1 "2.2nF" C0402#3 7641.2,8893.7 r90 top
C4$CBB9/CBB2 "2.2nF" C0402#3 7641.2,8373.7 r90 top
C4$CBB9/CBB3 "2.2nF" C0402#3 7641.2,7588.7 r90 top
C4$CBB9/CBB4 "2.2nF" C0402#3 7641.2,6803.7 r90 top
C4$CBB9/CBB5 "2.2nF" C0402#3 7641.2,6283.7 r90 top
C4$CBB9/CBB6 "2.2nF" C0402#3 7641.2,5498.7 r90 top
C4$CBB9/CBB7 "2.2nF" C0402#3 8149.9,8893.7 r90 top
C4$CBB9/CBB8 "2.2nF" C0402#3 8149.9,8373.7 r90 top
C4$CBB9/CBB9 "2.2nF" C0402#3 8149.9,7588.7 r90 top
C4$CBB9/CBB10 "2.2nF" C0402#3 8149.9,6803.7 r90 top
C4$CBB9/CBB11 "2.2nF" C0402#3 8149.9,6283.7 r90 top
C4$CBB9/CBB12 "2.2nF" C0402#3 8149.9,5498.7 r90 top
C4$CBB9/CBB13 "2.2nF" C0402#3 8658.6,8893.7 r90 top
C4$CBB9/CBB14 "2.2nF" C0402#3 8658.6,8373.7 r90 top
C4$CBB9/CBB15 "2.2nF" C0402#3 8658.6,7588.7 r90 top
C4$CBB9/CBB16 "2.2nF" C0402#3 8658.6,6803.7 r90 top
C4$CBB9/CBB17 "2.2nF" C0402#3 8658.6,6283.7 r90 top
C4$CBB9/CBB18 "2.2nF" C0402#3 8658.6,5498.7 r90 top
C4$CBB9/CBB19 "2.2nF" C0402#3 9167.3,8893.7 r90 top
C4$CBB9/CBB20 "2.2nF" C0402#3 9167.3,8373.7 r90 top
C4$CBB9/CBB21 "2.2nF" C0402#3 9167.3,7588.7 r90 top
C4$CBB9/CBB22 "2.2nF" C0402#3 9167.3,6803.7 r90 top
C4$CBB9/CBB23 "2.2nF" C0402#3 9167.3,6283.7 r90 top
C4$CBB9/CBB24 "2.2nF" C0402#3 9167.3,5498.7 r90 top
C4$CBB9/CBB25 "2.2nF" C0402#3 9676,8893.7 r90 top
C4$CBB9/CBB26 "2.2nF" C0402#3 9676,8373.7 r90 top
C4$CBB9/CBB27 "2.2nF" C0402#3 9676,7588.7 r90 top
C4$CBB9/CBB28 "2.2nF" C0402#3 9676,6803.7 r90 top
C4$CBB9/CBB29 "2.2nF" C0402#3 9676,6283.7 r90 top
C4$CBB9/CBB30 "2.2nF" C0402#3 9676,5498.7 r90 top
C4$CBB9/CBB31 "2.2nF" C0402#3 10184.7,8893.7 r90 top
C4$CBB9/CBB32 "2.2nF" C0402#3 10184.7,8373.7 r90 top
C4$CBB9/CBB33 "2.2nF" C0402#3 10184.7,7588.7 r90 top
C4$CBB9/CBB34 "2.2nF" C0402#3 10184.7,6803.7 r90 top
C4$CBB9/CBB35 "2.2nF" C0402#3 10184.7,6283.7 r90 top
C4$CBB9/CBB36 "2.2nF" C0402#3 10184.7,5498.7 r90 top
C4$CBB9/CBB37 "2.2nF" C0402#3 7641.2,8108.7 r90 top
C4$CBB9/CBB38 "2.2nF" C0402#3 8149.9,8108.7 r90 top
C4$CBB9/CBB39 "2.2nF" C0402#3 8658.6,8108.7 r90 top
C4$CBB9/CBB40 "2.2nF" C0402#3 9167.3,8108.7 r90 top
C4$CBB9/CBB41 "2.2nF" C0402#3 9676,8108.7 r90 top
C4$CBB9/CBB42 "2.2nF" C0402#3 10184.7,8108.7 r90 top
C4$CBB21 "100nF" C0402#2 7087.1,4463.7 r180 top
C4$CBB23 "100nF" C0201 3940.5,5626.3 r0 bottom
C4$CBB49/CBB1 "2.2nF" C0402#3 7646.2,9148.7 r90 top
C4$CBB49/CBB2 "2.2nF" C0402#3 7646.2,8628.7 r90 top
C4$CBB49/CBB3 "2.2nF" C0402#3 7646.2,7843.7 r90 top
C4$CBB49/CBB4 "2.2nF" C0402#3 7646.2,7058.7 r90 top
C4$CBB49/CBB5 "2.2nF" C0402#3 7646.2,6538.7 r90 top
C4$CBB49/CBB6 "2.2nF" C0402#3 7646.2,5753.7 r90 top
C4$CBB49/CBB7 "2.2nF" C0402#3 8154.9,9148.7 r90 top
C4$CBB49/CBB8 "2.2nF" C0402#3 8154.9,8628.7 r90 top
C4$CBB49/CBB9 "2.2nF" C0402#3 8154.9,7843.7 r90 top
C4$CBB49/CBB10 "2.2nF" C0402#3 8154.9,7058.7 r90 top
C4$CBB49/CBB11 "2.2nF" C0402#3 8154.9,6538.7 r90 top
C4$CBB49/CBB12 "2.2nF" C0402#3 8154.9,5753.7 r90 top
C4$CBB49/CBB13 "2.2nF" C0402#3 8663.6,9148.7 r90 top
C4$CBB49/CBB14 "2.2nF" C0402#3 8663.6,8628.7 r90 top
C4$CBB49/CBB15 "2.2nF" C0402#3 8663.6,7843.7 r90 top
C4$CBB49/CBB16 "2.2nF" C0402#3 8663.6,7058.7 r90 top
C4$CBB49/CBB17 "2.2nF" C0402#3 8663.6,6538.7 r90 top
C4$CBB49/CBB18 "2.2nF" C0402#3 8663.6,5753.7 r90 top
C4$CBB49/CBB19 "2.2nF" C0402#3 9172.3,9148.7 r90 top
C4$CBB49/CBB20 "2.2nF" C0402#3 9172.3,8628.7 r90 top
C4$CBB49/CBB21 "2.2nF" C0402#3 9172.3,7843.7 r90 top
C4$CBB49/CBB22 "2.2nF" C0402#3 9172.3,7058.7 r90 top
C4$CBB49/CBB23 "2.2nF" C0402#3 9172.3,6538.7 r90 top
C4$CBB49/CBB24 "2.2nF" C0402#3 9172.3,5753.7 r90 top
C4$CBB49/CBB25 "2.2nF" C0402#3 9681,9148.7 r90 top
C4$CBB49/CBB26 "2.2nF" C0402#3 9681,8628.7 r90 top
C4$CBB49/CBB27 "2.2nF" C0402#3 9681,7843.7 r90 top
C4$CBB49/CBB28 "2.2nF" C0402#3 9681,7058.7 r90 top
C4$CBB49/CBB29 "2.2nF" C0402#3 9681,6538.7 r90 top
C4$CBB49/CBB30 "2.2nF" C0402#3 9681,5753.7 r90 top
C4$CBB49/CBB31 "2.2nF" C0402#3 10189.7,9148.7 r90 top
C4$CBB49/CBB32 "2.2nF" C0402#3 10189.7,8628.7 r90 top
C4$CBB49/CBB33 "2.2nF" C0402#3 10189.7,7843.7 r90 top
C4$CBB49/CBB34 "2.2nF" C0402#3 10189.7,7058.7 r90 top
C4$CBB49/CBB35 "2.2nF" C0402#3 10189.7,6538.7 r90 top
C4$CBB49/CBB36 "2.2nF" C0402#3 10189.7,5753.7 r90 top
C4$CBB49/CBB37 "2.2nF" C0402#3 7646.2,6018.7 r90 top
C4$CBB49/CBB38 "2.2nF" C0402#3 8154.9,6018.7 r90 top
C4$CBB49/CBB39 "2.2nF" C0402#3 8663.6,6018.7 r90 top
C4$CBB49/CBB40 "2.2nF" C0402#3 9172.3,6018.7 r90 top
C4$CBB49/CBB41 "2.2nF" C0402#3 9681,6018.7 r90 top
C4$CBB49/CBB42 "2.2nF" C0402#3 10189.7,6018.7 r90 top
C4$CBB49/CBB43 "2.2nF" C0402#3 7646.2,7323.7 r90 top
C4$CBB49/CBB44 "2.2nF" C0402#3 8154.9,7323.7 r90 top
C4$CBB49/CBB45 "2.2nF" C0402#3 8663.6,7323.7 r90 top
C4$CBB49/CBB46 "2.2nF" C0402#3 9172.3,7323.7 r90 top
C4$CBB49/CBB47 "2.2nF" C0402#3 9681,7323.7 r90 top
C4$CBB49/CBB48 "2.2nF" C0402#3 10189.7,7323.7 r90 top
C5 "100nF" C0201 5520.7,4505.9 r90 bottom
C5$CBB7 "100pF" C0402#3 6942.1,4860.7 r0 top
C5$CBB21 "100pF" C0402#3 7162.1,4860.7 r0 top
C5$CBB23 "100nF" C0201 3954.6,5736.7 r270 bottom
C6 "4.7uF" C0402#4 3884.3,9646 r180 top
C6$CBB7 "100pF" C0402#3 6942.1,4658.7 r0 top
C6$CBB21 "100pF" C0402#3 7162.1,4658.7 r0 top
C6$CBB23 "100nF" C0201 4065,5626.3 r180 bottom
C7 "22uF" C2220#2 3620.5,9177.4 r0 top
C7$CBB7 "100nF" C0402#2 6867.1,4263.7 r180 top
C7$CBB21 "100nF" C0402#2 7087.1,4658.7 r180 top
C7$CBB23 "100nF" C0201 4081.1,5704.6 r270 bottom
C8 "100nF" C0201 5550.8,4421.5 r0 bottom
C8$CBB7 "100pF" C0402#3 6942.1,4463.7 r0 top
C8$CBB21 "100pF" C0402#3 7157.1,4463.7 r0 top
C8$CBB23 "100nF" C0201 4018.8,5642.3 r90 bottom
C9 "100nF" C0201 5645.2,4437.6 r90 bottom
C9$CBB7 "100pF" C0402#3 6942.1,4263.7 r0 top
C9$CBB21 "100pF" C0402#3 7157.1,4263.7 r0 top
C9$CBB23 "100nF" C0201 3970.6,5658.4 r0 bottom
C10 "100nF" C0201 5560.9,4377.4 r270 bottom
C10$CBB7 "100pF" C0402#3 6942.1,4063.7 r0 top
C10$CBB21 "100pF" C0402#3 7157.1,4065.7 r0 top
C10$CBB23 "100nF" C0201 3910.4,5658.4 r180 bottom
C11 "100nF" C0201 5615.1,4365.3 r0 bottom
C11$CBB7 "100pF" C0402#3 6942.1,3863.7 r0 top
C11$CBB21 "100pF" C0402#3 7158.1,3862.8 r0 top
C11$CBB23 "100nF" C0201 3986.7,5736.7 r270 bottom
C12 "100nF" C0201 5679.3,4367.3 r270 bottom
C12$CBB23 "100nF" C0201 4018.8,5736.7 r270 bottom
C13 "100nF" C0201 5647.2,4548 r90 bottom
C13$CBB23 "100nF" C0201 4032.9,5594.1 r180 bottom
C14 "100nF" C0201 5542.8,4610.3 r270 bottom
C14$CBB23 "100nF" C0201 4095.1,5660.4 r0 bottom
C15 "100nF" C0201 5683.3,4610.3 r90 bottom
C15$CBB23 "100nF" C0201 3910.4,5690.5 r180 bottom
C16 "100nF" C0201 5464.5,4560.1 r90 bottom
C16$CBB23 "100nF" C0201 3970.6,5690.5 r0 bottom
C17 "100nF" C0201 5494.6,4560.1 r270 bottom
C17$CBB23 "100nF" C0201 3880.3,5564 r180 bottom
C18 "100nF" C0201 5611.1,4602.2 r90 bottom
C18$CBB23 "100nF" C0201 3970.6,5594.1 r0 bottom
C19 "100nF" C0201 5460.5,4505.9 r90 bottom
C19$CBB23 "100nF" C0201 4081.1,5580.1 r270 bottom
C20 "100nF" C0201 5512.7,4612.3 r90 bottom
C20$CBB23 "100nF" C0201 4048.9,5672.4 r90 bottom
C21 "100nF" C0201 5597,4467.7 r0 bottom
C21$CBB23 "100nF" C0201 4050.9,5736.7 r270 bottom
C22 "100nF" C0201 5490.6,4481.8 r90 bottom
C22$CBB22/CBB4 "100nF" C0201 5605,4686.6 r90 bottom
C22$CBB23 "100nF" C0201 4050.9,5796.9 r90 bottom
C23 "100nF" C0201 5791.8,4339.2 r270 bottom
C23$CBB22/CBB4 "100nF" C0201 5542.8,4698.6 r270 bottom
C23$CBB23 "100nF" C0201 3908.4,5724.6 r180 bottom
C24 "100nF" C0201 5536.8,4463.7 r0 bottom
C24$CBB22/CBB4 "100nF" C0201 5669.3,4686.6 r90 bottom
C25 "100nF" C0201 5426.3,4465.7 r0 bottom
C25$CBB22/CBB4 "100nF" C0201 5683.3,4762.9 r90 bottom
C26 "100nF" C0201 5607,4762.9 r90 bottom
C27 "100nF" C0201 5528.7,4654.4 r0 bottom
C28 "100nF" C0201 5412.9,4508.2 r90 bottom
C29 "47uF" C1206 3663,9449.9 r0 top
C30 "47uF" C1206 3663,9354.9 r0 top
C31 "4.7uF" C0402#1 3522.9,6499.7 r0 top
C32 "47uF" C1206 3606.1,6573.3 r180 top
C32$CBB23 "47uF" C1206 4514.8,9664.1 r180 top
C33 "4.7nF" C0402#4 3607.2,6485.6 r180 bottom
C34 "12pF" C0402#5 3791.1,6543.3 r90 top
C35 "22uF" C2220#1 3250.7,7870.6 r0 top
C36 "100nF" C0402#1 3742.9,8721.3 r270 top
C37 "47uF" C1206 3592.9,8421.3 r90 top
C38 "4.7uF" C0402#5 3336.1,8210.4 r0 top
C39 "47uF" C1206 3396.1,6573.3 r180 top
C40 "4.7nF" C0402#1 3716.1,6428.3 r180 top
C41 "1uF" C0402#5 3616.1,6338.3 r0 top
C42 "100nF" C0402#1 3157.4,3935.6 r180 top
C43 "4.7uF" C0402#4 3530.9,7005.7 r180 top
C43$CBB22/CBB1 "100nF" C0402#5 5372,3688.5 r180 bottom
C44 "47uF" C1206 3606.1,7085.2 r180 top
C45 "4.7nF" C0402#1 3807.9,7988.2 r90 top
C46 "100nF" C0402#5 4382.9,4508.2 r180 top
C47 "100nF" C0402#1 3822.9,8093.2 r90 top
C48 "4.7nF" C0402#4 3607.2,7001.7 r180 bottom
C49 "12pF" C0402#1 3791.1,7055.2 r90 top
C50 "47uF" C1206 3290.7,8135.6 r0 top
C51 "47uF" C1206 3290.7,8040.6 r0 top
C52 "100nF" C0201 5631.1,4395.4 r0 bottom
C53 "47uF" C1206 3396.1,7085.2 r180 top
C54 "4.7nF" C0402#1 3716.1,6940.2 r180 top
C55 "100nF" C0402#1 3570.7,7990.6 r180 top
C55$CBB22/CBB2 "12pF" C0402#1 4286.3,4296.4 r180 top
C56 "3.3nF" C0402#2 4187.3,9198.2 r0 top
C56$CBB22/CBB2 "12pF" C0402#5 4176.3,4086.4 r0 top
C57 "1uF" C0402#5 3616.1,6850.2 r0 top
C57$CBB22 "100nF" C0402#1 5014.7,4048.1 r180 bottom
C58 "47pF" C0402#3 4127.3,9178.2 r270 top
C58$CBB22/CBB1 "100nF" C0402#5 6305.7,3688 r180 bottom
C59 "100nF" C0402#1 3940.5,9307.4 r180 top
C59$CBB22/CBB1 "100nF" C0402#1 6414.1,3663.9 r270 bottom
C60 "4.7uF" C0402#5 3526.9,7517.7 r180 top
C61 "47uF" C1206 3606.1,7597 r180 top
C62 "3.3nF" C0402#3 3815.7,7885.6 r0 top
C63 "100nF" C0402#1 4987.6,3990.9 r90 top
C64 "4.7nF" C0402#4 3607.2,7513.7 r180 bottom
C65 "12pF" C0402#1 3791.1,7567 r90 top
C66 "47uF" C1206 3396.1,7597 r180 top
C67 "4.7uF" C0402#5 3516.8,8473.4 r90 top
C68 "4.7nF" C0402#1 3716.1,7452 r180 top
C69 "47pF" C0402#3 3750.7,7865.6 r270 top
C70 "1uF" C0402#5 3616.1,7362 r0 top
C71 "47uF" C1206 3687.9,8421.3 r90 top
C72 "22uF" C2220#2 3872.9,8396.3 r90 top
C73 "3.3nF" C0402#3 3852.9,8971.3 r90 top
C74 "47pF" C0402#2 3872.9,8906.3 r0 top
C75 "330uF" CAP-SMD_BD6.3-L6.6-W6.6-FD#1 4354.1,8340.9 r180 top
C76 "330uF" CAP-SMD_BD6.3-L6.6-W6.6-FD#2 4625.2,5815 r180 top
C77 "330uF" CAP-SMD_BD6.3-L6.6-W6.6-FD#2 6050.8,4612.3 r90 top
C78 "100nF" C0201 5683.3,4532 r270 bottom
C79 "330uF" CAP-SMD_BD6.3-L6.6-W6.6-FD#2 4063,7302.8 r0 top
C80 "330uF" CAP-SMD_BD6.3-L6.6-W6.6-FD#2 3655.4,6146.3 r0 top
C81 "100uF" CAP-SMD_BD10.0-L10.3-W10.3-LS11.0-FD#1 4380.2,8774.6 r270 top
C82 "330uF" CAP-SMD_BD8.0-L8.3-W8.3-FD 4836,9565.7 r90 top
C83 "100uF" CAP-SMD_BD10.0-L10.3-W10.3-LS11.0-FD#2 4127.2,7658.2 r0 top
C84 "100nF" C0402#6 7355.9,4989.8 r0 top
C121$CBB22/CBB2 "4.7uF" C0402#5 4382.9,4463.2 r180 top
C122$CBB22/CBB2 "4.7uF" C0402#5 4487.9,4313.2 r270 bottom
C123$CBB22/CBB2 "100nF" C0402#5 4447.9,4313.2 r270 bottom
C125$CBB22/CBB2 "100nF" C0402#1 4487.9,4478.2 r90 top
C126$CBB22/CBB2 "100nF" C0402#1 4647.9,4208.2 r90 bottom
C127$CBB22/CBB2 "100nF" C0402#5 4617.9,4313.2 r270 bottom
C128$CBB22/CBB2 "100nF" C0402#5 4657.9,4313.2 r270 bottom
C132$CBB22/CBB2 "100nF" C0402#1 4467.9,4213.2 r90 bottom
C133$CBB22/CBB2 "100nF" C0402#5 4527.9,4313.2 r270 bottom
C134$CBB22/CBB2 "4.7uF" C0402#5 4357.9,4098.2 r270 bottom
C136$CBB22/CBB2 "4.7uF" C0402#1 4147.9,4098.2 r90 bottom
C138$CBB22/CBB4 "10uF" C0402#1 5801.8,4443.6 r270 bottom
C142$CBB22/CBB4 "10uF" C0402#1 5850,4248.9 r90 bottom
C145$CBB15 "100nF" C0402#3 8336.1,4109.2 r180 top
C146$CBB15 "100nF" C0402#2 7657.4,4278.4 r270 top
C147$CBB22/CBB4 "10uF" C0402#1 5936.3,4299.1 r90 bottom
C147$CBB23 "10uF" C0402#1 3723.7,5726.7 r0 bottom
C168 "100nF" C0201 5516.7,4377.4 r270 bottom
C169 "100nF" C0201 5239.6,4367.3 r90 bottom
C170 "100nF" C0201 5464.5,4431.6 r90 bottom
C171 "100nF" C0201 5273.7,4367.3 r90 bottom
C172 "100nF" C0201 5587,4530 r90 bottom
C173 "100nF" C0201 5464.5,4375.4 r90 bottom
C174 "100nF" C0201 5239.6,4764.9 r270 bottom
C175 "100nF" C0201 5464.5,4710.7 r90 bottom
C176 "100nF" C0201 5271.7,4469.7 r180 bottom
C177 "100nF" C0201 5376.1,4724.7 r180 bottom
C178 "100nF" C0201 5350,4391.4 r0 bottom
C179 "100nF" C0201 5402.9,4568.2 r180 bottom
C180 "100nF" C0201 5273.7,4764.9 r270 bottom
C181 "100nF" C0201 5325.9,4469.7 r0 bottom
C183$CBB24 "100nF" C0402#4 3071.7,4055.6 r270 top
C184$CBB24 "10pF" C0402#5 3355.7,3828.7 r270 top
C185$CBB24 "10pF" C0402#1 3160.7,3828.7 r90 top
C186$CBB24 "100nF" C0201 3074.6,4423.9 r90 top
C188$CBB24 "100nF" C0201 3536.9,3869.4 r0 top
C193$CBB1 "100nF" C0402#2 7467.1,4822.2 r90 top
C193$CBB2 "100nF" C0402#2 7975.8,4822.2 r90 top
C193$CBB3 "100nF" C0402#2 8484.5,4822.2 r90 top
C193$CBB4 "100nF" C0402#2 8993.2,4822.2 r90 top
C193$CBB5 "100nF" C0402#2 9501.9,4822.2 r90 top
C193$CBB6 "100nF" C0402#2 10010.6,4822.2 r90 top
C193$CBB7 "100nF" C0402#2 6867.1,3863.7 r180 top
C193$CBB8 "100nF" C0402#2 7826.9,4862.6 r270 bottom
C193$CBB10 "100nF" C0402#2 8335.6,4862.6 r270 bottom
C193$CBB11 "100nF" C0402#2 8844.3,4862.6 r270 bottom
C193$CBB12 "100nF" C0402#2 9353,4862.6 r270 bottom
C193$CBB13 "100nF" C0402#2 9861.7,4862.6 r270 bottom
C193$CBB14 "100nF" C0402#2 10370.4,4862.6 r270 bottom
C193$CBB16 "100nF" C0402#2 4792.1,8248.7 r180 bottom
C193$CBB16/CBB1 "100nF" C0402#3 5093.8,8740.1 r180 top
C193$CBB16/CBB2 "100nF" C0402#3 5093.8,9192.8 r180 top
C193$CBB16/CBB3 "100nF" C0402#3 5093.8,8287.3 r180 top
C193$CBB16/CBB4 "100nF" C0402#3 5093.8,7834.5 r180 top
C193$CBB16/CBB5 "100nF" C0402#3 5093.8,7381.8 r180 top
C193$CBB16/CBB6 "100nF" C0402#3 5093.8,6929.1 r180 top
C193$CBB17 "100nF" C0402#2 5417.5,8250.1 r180 bottom
C193$CBB17/CBB1 "100nF" C0402#3 5718.8,9192.8 r180 top
C193$CBB17/CBB2 "100nF" C0402#3 5718.8,8740.1 r180 top
C193$CBB17/CBB3 "100nF" C0402#3 5718.8,8287.3 r180 top
C193$CBB17/CBB4 "100nF" C0402#3 5718.8,7834.6 r180 top
C193$CBB17/CBB5 "100nF" C0402#3 5718.8,7381.8 r180 top
C193$CBB17/CBB6 "100nF" C0402#3 5718.8,6929 r180 top
C193$CBB17/CBB7 "100nF" C0402#3 5718.8,6476.3 r180 top
C193$CBB17/CBB8 "100nF" C0402#3 5718.8,6023.5 r180 top
C193$CBB18 "100nF" C0402#2 6047.4,8250.1 r180 bottom
C193$CBB18/CBB1 "100nF" C0402#6 6348.7,9192.8 r180 top
C193$CBB18/CBB2 "100nF" C0402#6 6348.7,8740.1 r180 top
C193$CBB18/CBB3 "100nF" C0402#6 6348.7,8287.3 r180 top
C193$CBB18/CBB4 "100nF" C0402#6 6348.7,7834.6 r180 top
C193$CBB18/CBB5 "100nF" C0402#6 6348.7,7381.8 r180 top
C193$CBB18/CBB6 "100nF" C0402#6 6348.7,6929 r180 top
C193$CBB18/CBB7 "100nF" C0402#6 6348.7,6476.3 r180 top
C193$CBB18/CBB8 "100nF" C0402#6 6348.7,6023.5 r180 top
C193$CBB20 "100nF" C0402#3 6677.4,8250.1 r180 bottom
C193$CBB20/CBB1 "100nF" C0402#2 6978.6,9192.8 r180 top
C193$CBB20/CBB2 "100nF" C0402#2 6978.6,8740.1 r180 top
C193$CBB20/CBB3 "100nF" C0402#2 6978.6,8287.3 r180 top
C193$CBB20/CBB4 "100nF" C0402#2 6978.6,7834.6 r180 top
C193$CBB20/CBB5 "100nF" C0402#2 6978.6,7381.8 r180 top
C193$CBB20/CBB6 "100nF" C0402#2 6978.6,6929 r180 top
C193$CBB20/CBB7 "100nF" C0402#2 6978.6,6476.3 r180 top
C193$CBB20/CBB8 "100nF" C0402#2 6978.6,6023.5 r180 top
C193$CBB21 "100nF" C0402#2 7088.1,3862.8 r180 top
C194$CBB9 "100nF" C0402#2 8262.1,5208.4 r180 top
C194$CBB19 "100nF" C0402#2 8262.1,5207.2 r180 bottom
C195$CBB9 "100nF" C0402#3 7436,5210.8 r270 top
C195$CBB19 "100nF" C0402#2 9282.1,5207.2 r180 bottom
C195$CBB49 "100nF" C0402#2 7842.1,5208.4 r180 top
C196$CBB9 "100nF" C0402#2 10302.1,5208.4 r180 top
C196$CBB19 "100nF" C0402#2 10302.1,5207.2 r180 bottom
C196$CBB49 "100nF" C0402#2 8859.5,5208.4 r180 top
C197$CBB9 "100nF" C0402#2 9282.1,5208.4 r180 top
C197$CBB19 "100nF" C0402#2 7842.1,5207.2 r180 bottom
C197$CBB49 "100nF" C0402#2 9876.9,5208.4 r180 top
C212$CBB24 "4.7uF" C0402#1 3140.9,4445.9 r0 top
C213$CBB24 "100nF" C0201 3074.6,4323.5 r90 top
C214$CBB24 "100nF" C0201 3438.5,3869.4 r0 top
C215$CBB24 "4.7uF" C0402#1 3142.9,4345.6 r0 top
C217$CBB24 "4.7uF" C0402#1 3310,4275 r90 bottom
C218$CBB24 "100nF" C0201 3265.9,4345.2 r180 top
C219$CBB24 "100nF" C0201 3607.2,4433.6 r0 top
C220$CBB24 "4.7uF" C0402#5 3713.6,4064.1 r0 bottom
C221$CBB24 "100nF" C0201 3235.7,4262.9 r270 top
C222$CBB24 "100nF" C0201 3462.6,4433.6 r180 top
C223$CBB24 "100nF" C0201 3223.7,4176.6 r90 top
C224$CBB24 "100nF" C0201 3810,4062.1 r0 top
C225$CBB23 "100nF" C0402#4 3083.1,5943.5 r270 top
C226$CBB24 "100nF" C0402#1 3743.7,3423.6 r180 top
C227$CBB22 "100nF" C0402#1 4387.7,5151.6 r180 top
C248 "100nF" C0201 5542.8,4560.1 r270 bottom
C250 "100nF" C0201 5440.4,4612.3 r270 bottom
C258 "100nF" C0201 5410.3,4612.3 r90 bottom
C313 "100nF" C0201 5552.8,4505.9 r270 bottom
C314 "100nF" C0201 5470.5,4612.3 r90 bottom
C315 "100nF" C0402#1 4597.9,4173.2 r90 bottom
C316 "100nF" C0402#1 4517.9,4173.2 r90 bottom
D1 "PESD1642U005" D0402-BI#1 5364.1,3391.5 r180 top locked
D1$CBB24 "USBLC6-2SC6" SOT-23-6_L2.9-W1.6-P0.95-LS2.8-BL 3739.7,3526 r180 top
D2 "PESD1642U005" D0402-BI#1 5269.7,3391.5 r0 top locked
D3 "PESD1642U005" D0402-BI#1 5153.3,3437.7 r0 top locked
D4 "PESD1642U005" D0402-BI#2 5247.6,3437.7 r180 top locked
D5 "PESD1642U005" D0402-BI#1 5034.8,3393.5 r0 top locked
D6 "PESD1642U005" D0402-BI#3 5127.2,3393.5 r180 top locked
D7 "PESD1642U005" D0402-BI#1 6251.6,3411.6 r270 top locked
D8 "PESD1642U005" D0402-BI#1 6129.1,3411.6 r270 top locked
D9 "PESD1642U005" D0402-BI#1 6209.4,3411.6 r270 top locked
D10 "PESD1642U005" D0402-BI#1 6082.9,3411.6 r270 top locked
D11 "PESD1642U005" D0402-BI#1 6008.6,3411.6 r270 top locked
D12 "PESD1642U005" D0402-BI#1 6327.9,3411.6 r270 top locked
D13 "PESD1642U005" D0402-BI#1 5542.8,3413.6 r270 top
D14 "PESD1642U005" D0402-BI#1 5496.6,3413.6 r270 top
D15 "PESD1642U005" D0402-BI#1 5442.4,3411.6 r270 top
D16 "PESD1642U005" D0402-BI#1 6506.6,3411.6 r270 top
D17 "PESD1642U005" D0402-BI#1 6464.4,3411.6 r270 top
D18 "PESD1642U005" D0402-BI#1 6384.1,3411.6 r270 top
D19 "RBR5L60ADDTE25" SMA_L4.5-W2.6-LS5.0-RD 3261.8,9198.3 r0 top
ETH-LED1 "KT-0603R" LED0603-RD#1 4112,4431.6 r0 top
FPC1$CBB22/CBB1 "522711579" FPC-SMD_522711579#1 6267.6,3265 r0 top locked
FPC3$CBB22/CBB1 "522711579" FPC-SMD_522711579#2 5297.8,3265 r0 top locked
H1$CBB8 "PZ254-1-03-Z-8.5" HDR-TH_03P-P2.54-V-M 7452.1,4492.2 r90 top
H1$CBB10 "PZ254-1-03-Z-8.5" HDR-TH_03P-P2.54-V-M 7960.8,4492.2 r90 top
H1$CBB11 "PZ254-1-03-Z-8.5" HDR-TH_03P-P2.54-V-M 8469.5,4492.2 r90 top
H1$CBB12 "PZ254-1-03-Z-8.5" HDR-TH_03P-P2.54-V-M 8978.2,4492.2 r90 top
H1$CBB13 "PZ254-1-03-Z-8.5" HDR-TH_03P-P2.54-V-M 9486.9,4492.2 r90 top
H1$CBB14 "PZ254-1-03-Z-8.5" HDR-TH_03P-P2.54-V-M 9995.6,4492.2 r90 top
L1 "1.5uH" IND-SMD_L7.8-W7.0_GCD75#1 3243.8,8937.2 r270 top
L2 "6.8uH" IND-SMD_L6.6-W6.6#1 3945.5,9477.4 r180 top
L3 "6.8uH" IND-SMD_L6.6-W6.6#2 3580.7,8160.6 r180 top
L4 "1.5uH" IND-SMD_L7.8-W7.0_GCD75#2 3280.3,6339.8 r0 top
L5 "1.5uH" IND-SMD_L7.8-W7.0_GCD75#2 3280.3,6851.6 r0 top
L6 "6.8uH" IND-SMD_L6.6-W6.6#1 3572.9,8721.3 r270 top
L7 "1.5uH" IND-SMD_L7.8-W7.0_GCD75#2 3280.3,7363.4 r0 top
L8 "HR911130C" RJ45-TH_HR911130C 4427.9,3563.6 r180 top locked
L9$CBB22/CBB4 "BLM15AX221SN1D" L0402#1 5878.1,4421.5 r180 bottom
L10$CBB22/CBB4 "BLM15AX221SN1D" L0402#2 5944.4,4226.8 r180 bottom
L11$CBB22/CBB4 "BLM15AX221SN1D" L0402#3 5980.5,4299.1 r90 bottom
L11$CBB23 "BLM15AX221SN1D" L0402#3 3721.7,5772.8 r0 bottom
L12 "4.7uH" IND-SMD_L7.8-W7.0_SUMIDA_CD73 4290.6,4696.3 r0 top
L13 "APBD2012-152WTD12" L0805 4252.9,4093.2 r0 bottom
LED1 "KT-0603R" LED0603-RD#1 3501.4,9374.2 r90 top
LED1$CBB15 "KT-0603R" LED0603-RD#2 9768.1,4178.4 r0 top
LED1$CBB22 "KT-0603R" LED0603-RD#1 4956.6,5271.4 r180 top
LED1$CBB23 "KT-0603R" LED0603-RD#1 3485.3,5911 r270 top
LED2 "KT-0603R" LED0603-RD#3 3149.4,8060.4 r90 top
LED2$CBB15 "KT-0603R" LED0603-RD#4 9889.5,4178.4 r0 top
LED2$CBB23 "KT-0603R" LED0603-RD#1 3358.8,5911 r270 top
LED3 "KT-0603R" LED0603-RD#1 3456.6,8429.8 r90 top
LED3$CBB15 "KT-0603R" LED0603-RD#2 10011,4178.4 r0 top
LED3$CBB23 "KT-0603R" LED0603-RD#1 3421.1,5911 r270 top
LED4$CBB15 "KT-0603R" LED0603-RD#5 10132.5,4178.4 r0 top
LED4$CBB23 "KT-0603R" LED0603-RD#6 4956.8,5398.3 r180 top
LED5 "KT-0603R" LED0603-RD#7 5163.2,3772.2 r270 top
LED5$CBB15 "KT-0603R" LED0603-RD#2 10253.9,4178.4 r0 top
LED5$CBB23 "KT-0603R" LED0603-RD#1 4956.8,5336.6 r180 top
LED6$CBB15 "KT-0603R" LED0603-RD#5 10375.4,4178.4 r0 top
LED6$CBB23 "KT-0603R" LED0603-RD#1 4956.8,5459.7 r180 top
LED7$CBB15 "KT-0603R" LED0603-RD#4 9039.3,4178.4 r0 top
LED7$CBB23 "KT-0603R" LED0603-RD#1 4956.8,5520.7 r180 top
LED8$CBB15 "KT-0603R" LED0603-RD#2 9160.8,4178.4 r0 top
LED8$CBB23 "KT-0603R" LED0603-RD#1 4956.8,5582.4 r180 top
LED9 "KT-0603R" LED0603-RD#1 4956.6,5207.2 r180 top
LED9$CBB15 "KT-0603R" LED0603-RD#4 9282.2,4178.4 r0 top
LED9$CBB23 "KT-0603R" LED0603-RD#7 8305.6,6039.9 r0 top
LED10$CBB15 "KT-0603R" LED0603-RD#2 9403.7,4178.4 r0 top
LED10$CBB23 "KT-0603R" LED0603-RD#7 9829.1,6033.3 r0 top
LED11$CBB15 "KT-0603R" LED0603-RD#5 9525.2,4178.4 r0 top
LED11$CBB23 "KT-0603R" LED0603-RD#3 8301.2,8144.7 r0 top
LED12$CBB15 "KT-0603R" LED0603-RD#2 9646.6,4178.4 r0 top
LED12$CBB23 "KT-0603R" LED0603-RD#3 3808.1,5070.6 r180 top
LED13$CBB23 "KT-0603R" LED0603-RD#3 9833.2,8143.8 r0 top
Q1$CBB1 "MMBT3904WT1G" SC-70-3_L2.1-W1.3-P1.30-LS2.1-BR#1 7582.4,4572.2 r180 top
Q1$CBB2 "MMBT3904WT1G" SC-70-3_L2.1-W1.3-P1.30-LS2.1-BR#1 8091.1,4572.2 r180 top
Q1$CBB3 "MMBT3904WT1G" SC-70-3_L2.1-W1.3-P1.30-LS2.1-BR#1 8599.8,4572.2 r180 top
Q1$CBB4 "MMBT3904WT1G" SC-70-3_L2.1-W1.3-P1.30-LS2.1-BR#1 9108.5,4572.2 r180 top
Q1$CBB5 "MMBT3904WT1G" SC-70-3_L2.1-W1.3-P1.30-LS2.1-BR#1 9617.2,4572.2 r180 top
Q1$CBB6 "MMBT3904WT1G" SC-70-3_L2.1-W1.3-P1.30-LS2.1-BR#1 10125.9,4572.2 r180 top
Q1$CBB8 "MMBT3904WT1G" SC-70-3_L2.1-W1.3-P1.30-LS2.1-BR#1 7691.9,4565.4 r0 bottom
Q1$CBB10 "MMBT3904WT1G" SC-70-3_L2.1-W1.3-P1.30-LS2.1-BR#1 8200.6,4565.4 r0 bottom
Q1$CBB11 "MMBT3904WT1G" SC-70-3_L2.1-W1.3-P1.30-LS2.1-BR#1 8709.3,4565.4 r0 bottom
Q1$CBB12 "MMBT3904WT1G" SC-70-3_L2.1-W1.3-P1.30-LS2.1-BR#1 9218,4565.4 r0 bottom
Q1$CBB13 "MMBT3904WT1G" SC-70-3_L2.1-W1.3-P1.30-LS2.1-BR#1 9726.7,4565.4 r0 bottom
Q1$CBB14 "MMBT3904WT1G" SC-70-3_L2.1-W1.3-P1.30-LS2.1-BR#1 10235.4,4565.4 r0 bottom
Q1$CBB15 "DOX3134A" SOT-323-3_L2.1-W1.3-P1.30-LS2.3-BR#1 9889.5,4101.7 r0 top
Q1$CBB22/CBB1 "BSS138" SOT-23-3_L2.9-W1.3-P1.90-LS2.4-BR-1#1 5414.3,3427.6 r90 bottom
Q1$CBB23 "DO2320AA" SOT-23-3_L2.9-W1.6-P1.90-LS2.8-BR#1 9713.1,9619.9 r0 top
Q2$CBB1 "MMBT3904WT1G" SC-70-3_L2.1-W1.3-P1.30-LS2.1-BR#2 7691.9,4572.2 r0 top
Q2$CBB2 "MMBT3904WT1G" SC-70-3_L2.1-W1.3-P1.30-LS2.1-BR#2 8200.6,4572.2 r0 top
